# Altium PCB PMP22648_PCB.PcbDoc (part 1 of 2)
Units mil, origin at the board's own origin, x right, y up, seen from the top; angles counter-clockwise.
Board outline 3299.21 x 2751.97 mil, 6 copper layers (Top Layer, GND, GND (Mid2), Signal Layer 3, GND (Mid4), Bottom Layer), stack 107.669 mil thick; 130 components, 60 nets, 290 pads, 212 vias.
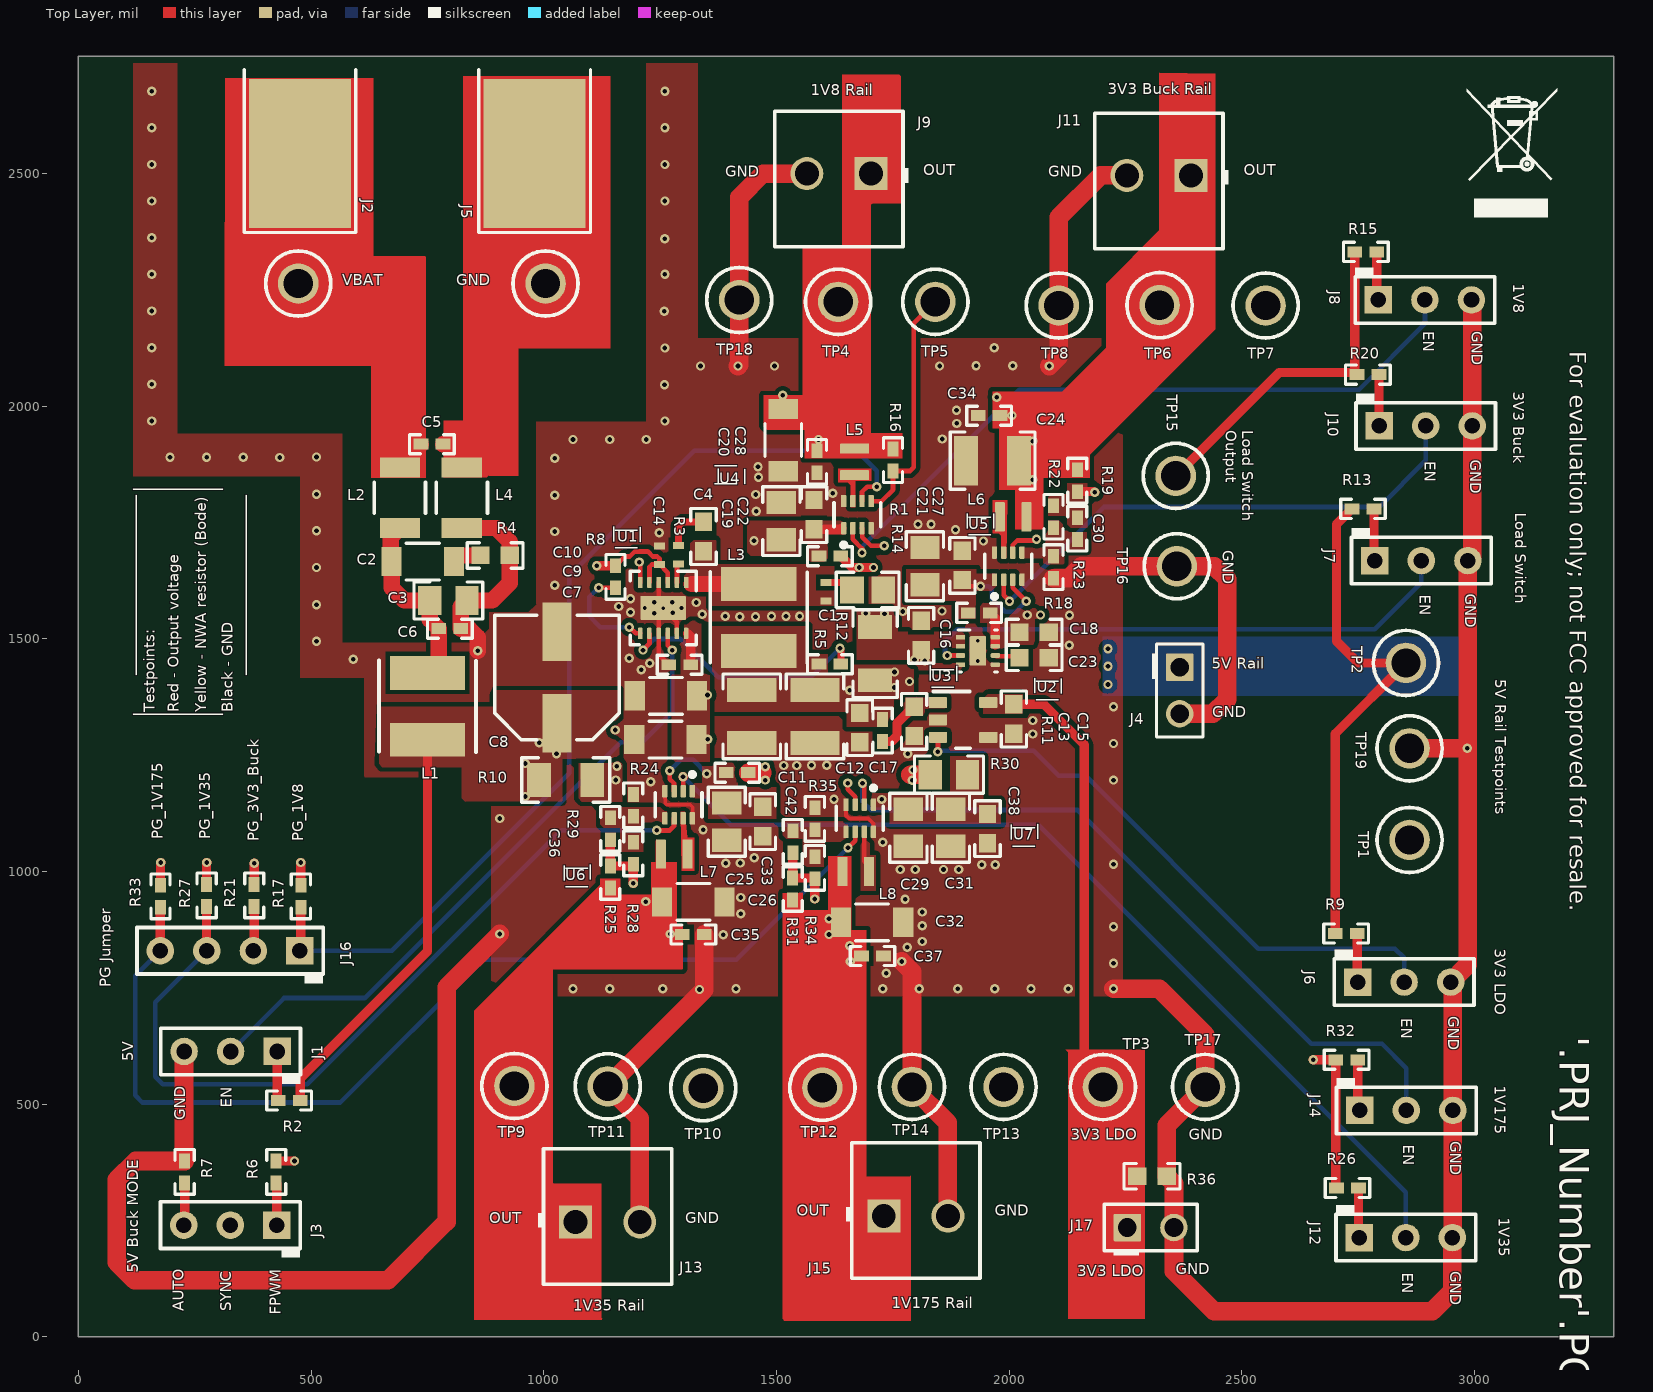
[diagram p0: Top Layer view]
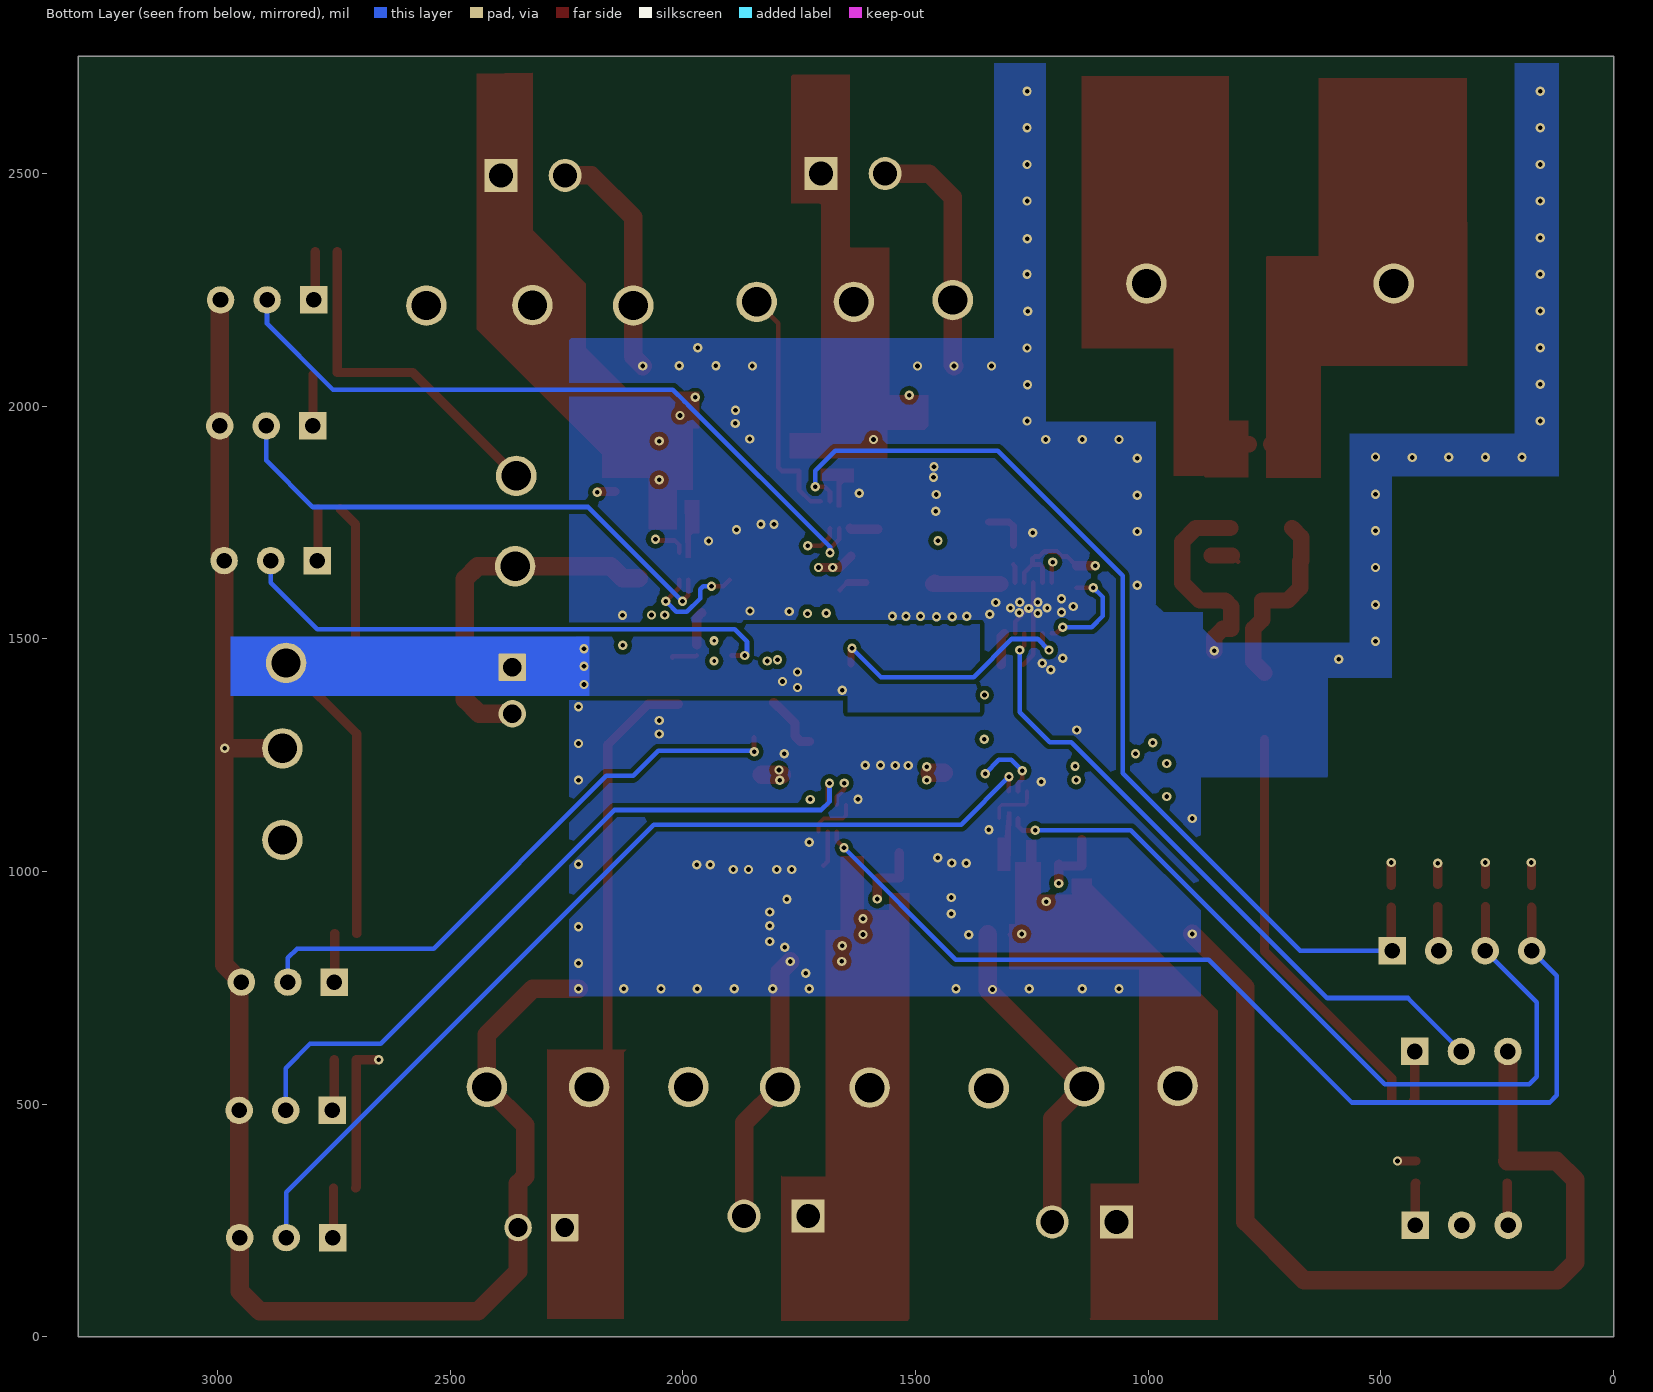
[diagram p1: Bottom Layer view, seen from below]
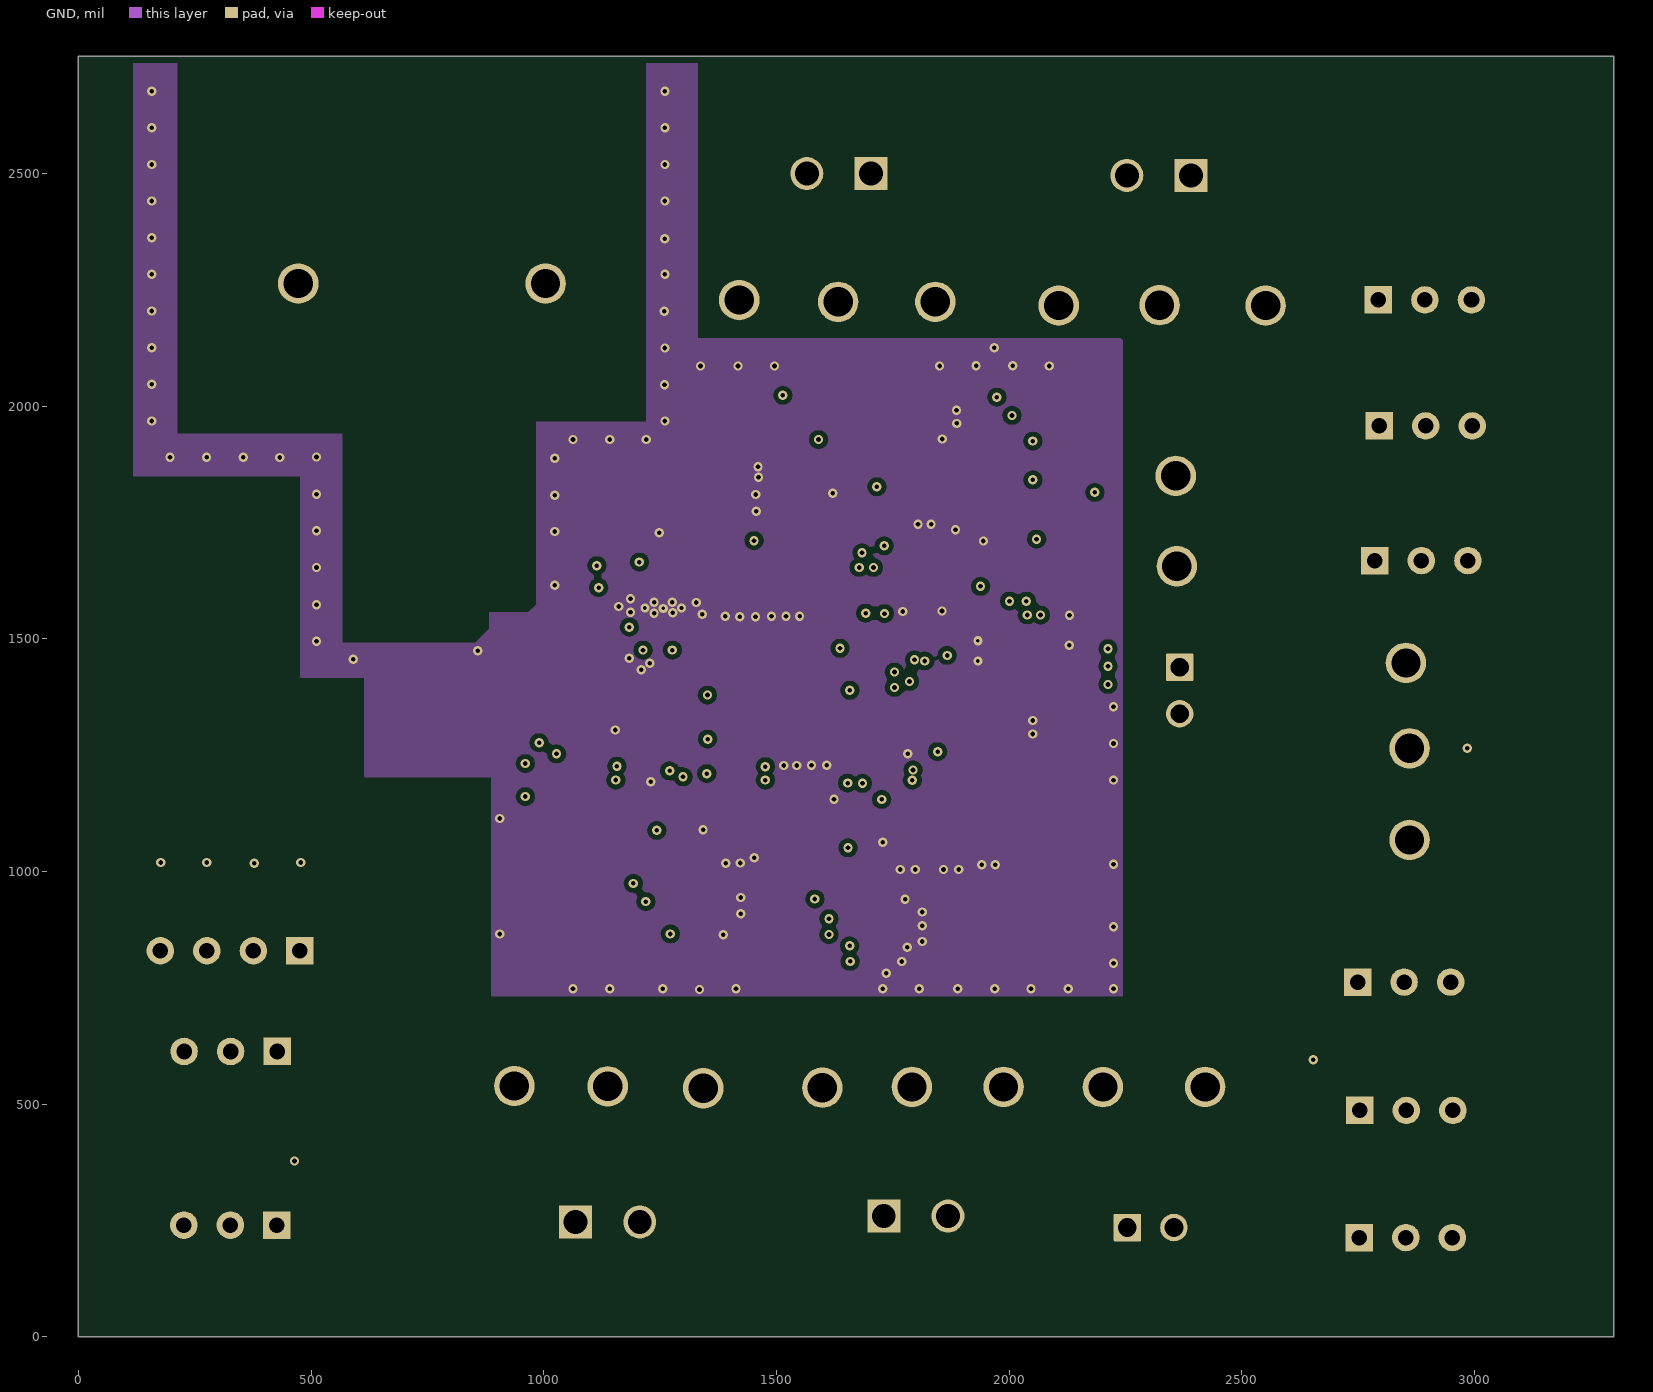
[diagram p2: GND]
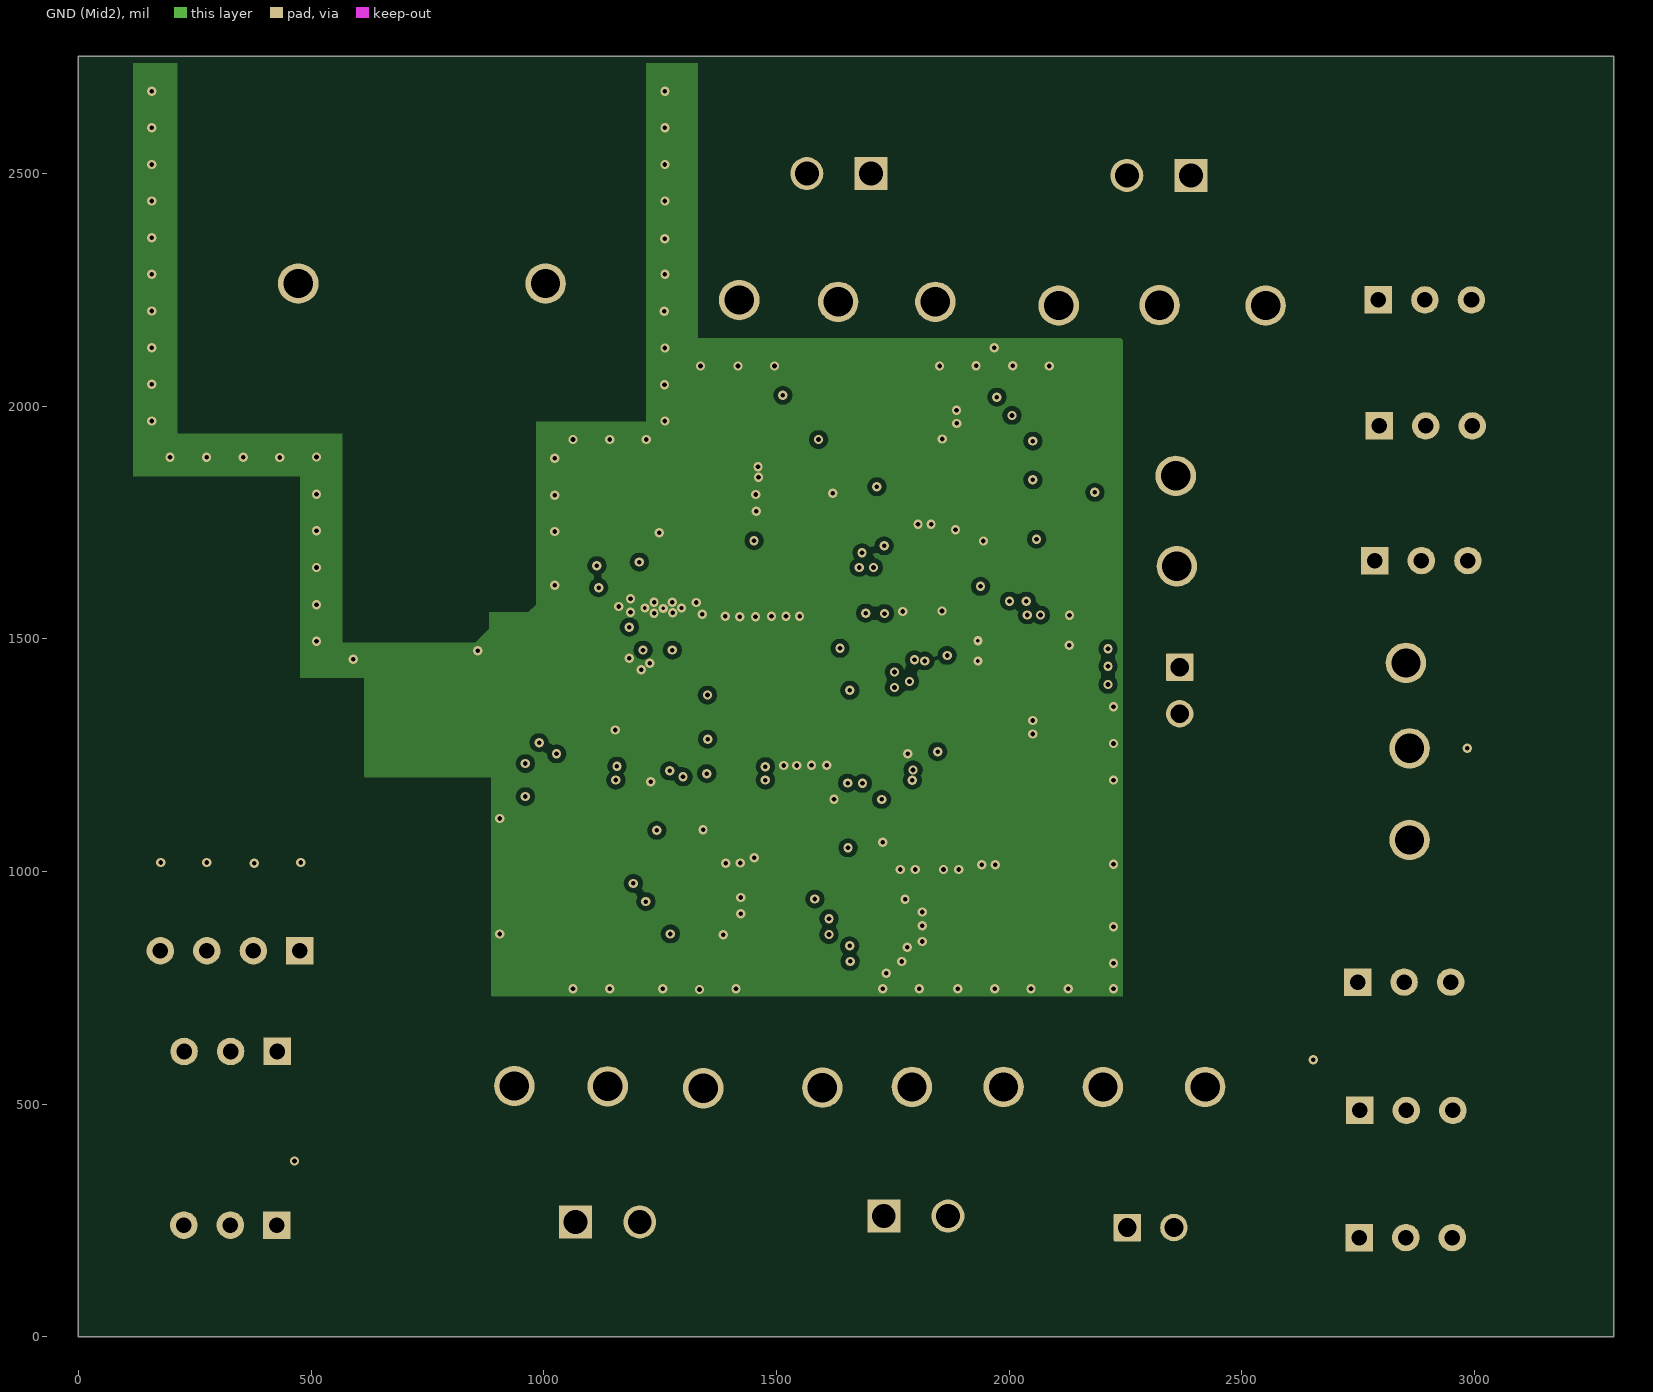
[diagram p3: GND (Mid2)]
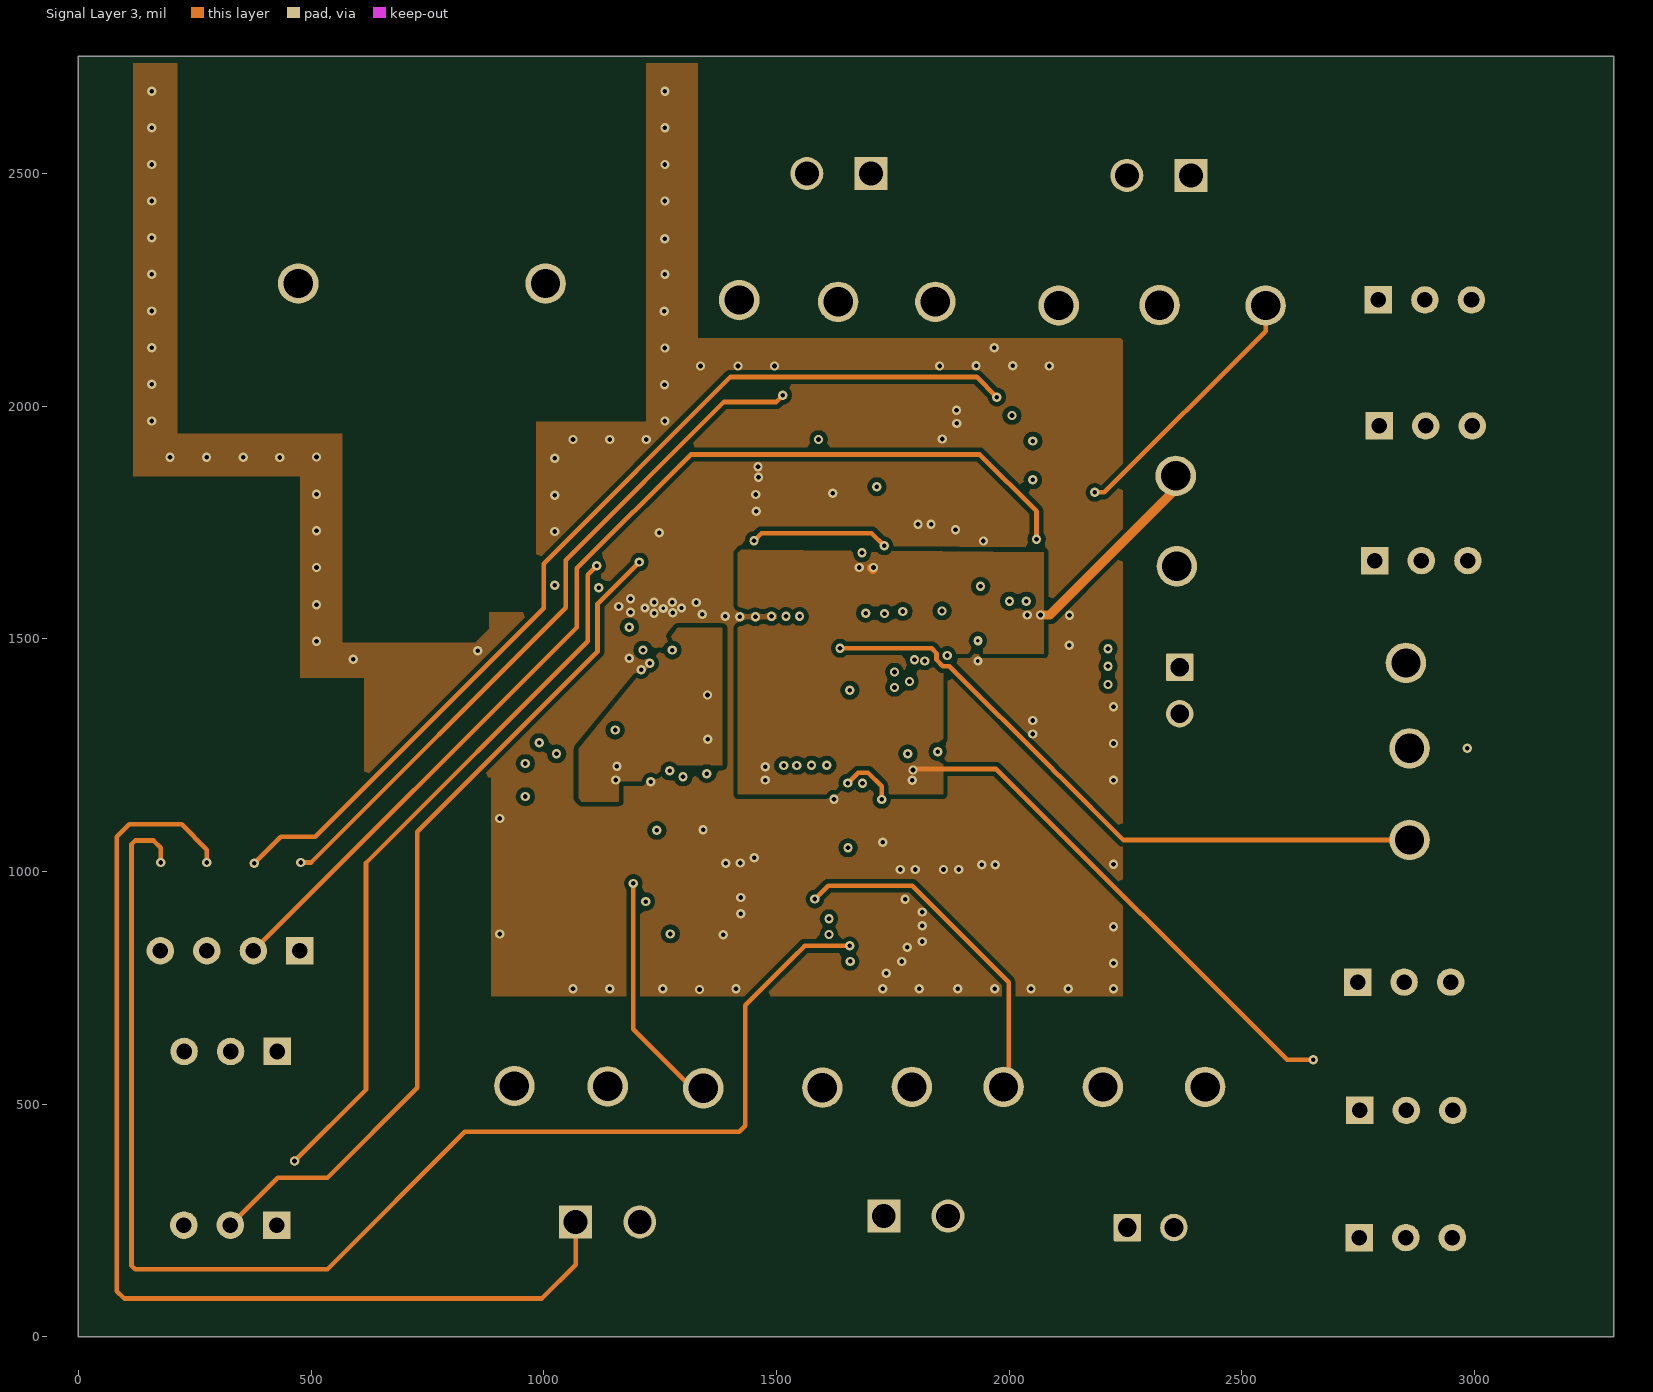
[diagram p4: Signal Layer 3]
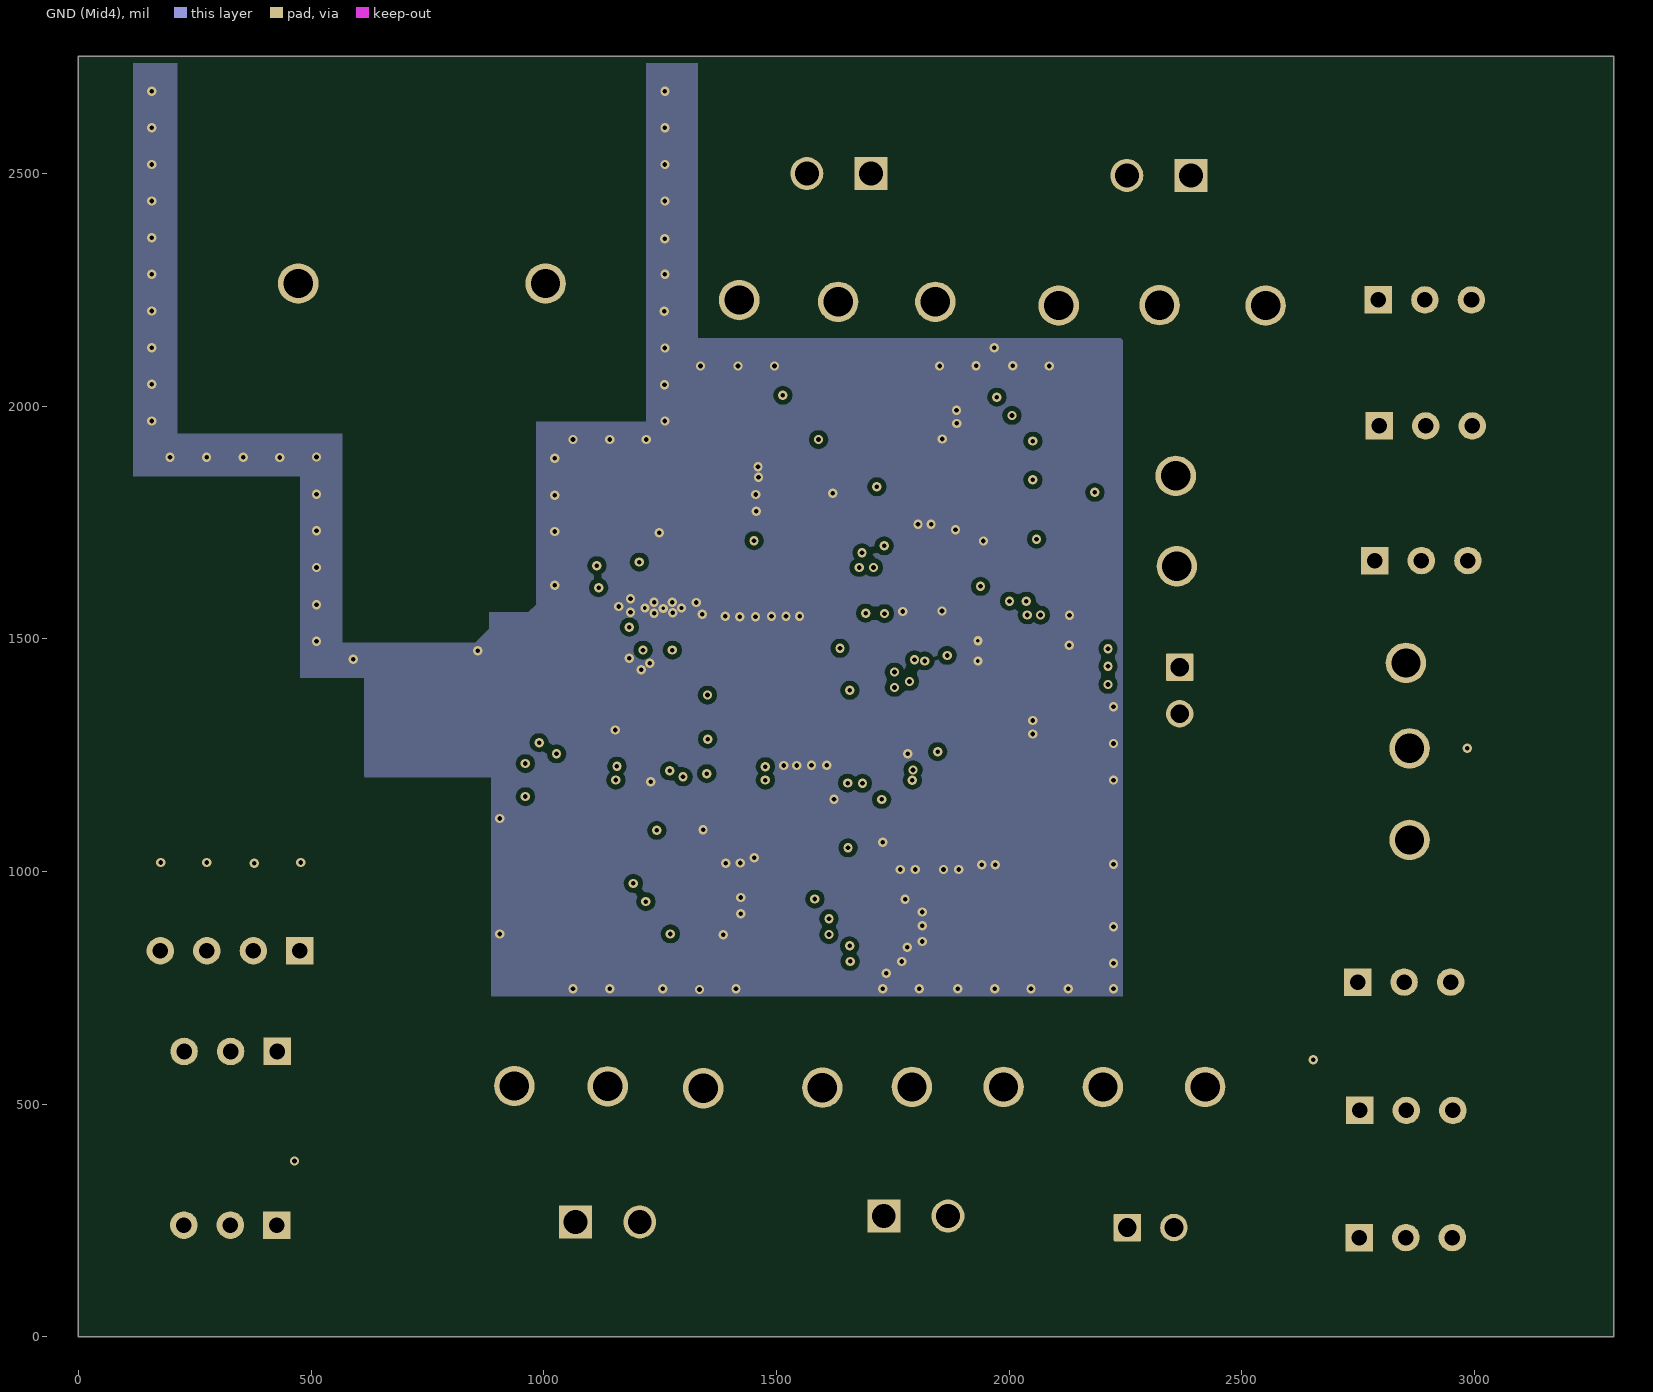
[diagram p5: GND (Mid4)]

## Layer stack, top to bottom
Top Solder: solder mask 0.4, Solder Resist, Dk 3.5
Top Layer: signal copper 1.4
Dielectric 2: dielectric 10, Dk 4.2
GND: signal copper 1.4173
Dielectric 3: dielectric 10, Dk 4.2
GND (Mid2): signal copper 1.4173
Dielectric1: core 59.2, FR-4, Dk 4.8
Signal Layer 3: signal copper 1.4173
Dielectric 4: dielectric 10, Dk 4.2
GND (Mid4): signal copper 1.4173
Dielectric 5: dielectric 10, Dk 4.2
Bottom Layer: signal copper 1.4
Bottom Solder: solder mask 0.4, Solder Resist, Dk 3.5

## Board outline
0,0 3299.21,0 3299.21,2751.97 0,2751.97

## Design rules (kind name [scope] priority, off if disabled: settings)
AcuteAngle [All] p1: minimum=4.50000000000000E+0001 checktracksonly=FALSE
AssemblyTestPointUsage [All] p1: valid=2
BoardOutlineClearance BoardOutlineClearance_MountingHoles [OnCopper and InComponentClass('Mounting Holes')] p1: gap=25 ignorepadtopadclearanceinfootprint=FALSE
BoardOutlineClearance BoardOutlineClearance_Poly [OnCopper and IsPoly] p2: gap=15 ignorepadtopadclearanceinfootprint=FALSE
BoardOutlineClearance [OnCopper and Not InComponentClass('Logo') and not InComponentClass('FiducialMark') and not InRegion(1000,500,4000,800) and not InPoly] p3: gap=30 ignorepadtopadclearanceinfootprint=FALSE
Clearance Clearance_1 [InNamedPolygon('TOP_LAYER_1V8_P020')] p1: gap=10 ignorepadtopadclearanceinfootprint=TRUE except(0: Arc-Hole Track-Hole SMDPad-Hole THPad-Hole Via-Hole Fill-Hole Poly-Hole Region-Hole Text-Hole)
Clearance Clearance_Keepouts [((IsTrack Or IsArc) And Not InPoly) And IsFree and IsKeepOut vs ((IsTrack Or IsArc) And Not InPoly) And IsFree and IsKeepOut] p2: gap=0 ignorepadtopadclearanceinfootprint=FALSE
Clearance Clearance_Poly [InPolygon] p3: gap=10 ignorepadtopadclearanceinfootprint=TRUE
Clearance Clearance_FiducialMark [IsKeepOut and InComponentClass('FiducialMark') vs IsPad and InComponentClass('FiducialMark')] p4: gap=0 ignorepadtopadclearanceinfootprint=FALSE
Clearance [All] p5: gap=7.87 ignorepadtopadclearanceinfootprint=TRUE
ComponentClearance ComponentClearance_MountingHoles_FiducialMarks [InComponentClass('Mounting Holes') vs InComponentClass('FiducialMark')] p1: gap=50 collisioncheckmode=3 verticalgap=10 showdistances=FALSE
ComponentClearance ComponentClearance_Shunt [InComponentClass('Header') vs InComponentClass('Shunt')] p2: gap=0 collisioncheckmode=3 verticalgap=0 showdistances=FALSE
ComponentClearance ComponentClearance_Logo [InComponentClass('Logo')] p3: gap=50 collisioncheckmode=3 verticalgap=10 showdistances=FALSE
ComponentClearance ComponentClearance_ScrewToNut [(HasFootprint('NY PMS 440 0025 PH')) vs (HasFootprint('Keystone_1902C'))] p4: gap=5 collisioncheckmode=3 verticalgap=10 showdistances=FALSE
ComponentClearance ComponentClearance_MountingHoles [InComponentClass('Mounting Holes')] p5: gap=250 collisioncheckmode=3 verticalgap=100000 showdistances=FALSE
ComponentClearance ComponentClearance_SmallPassives [HasFootprint('0201*') or HasFootprint('0402*') or HasFootprint('0508') or HasFootprint('0603*') or HasFootprint('0612') or HasFootprint('0805*') or HasFootprint('0815*') or HasFootprint('0830*') or HasFootprint('1206*') or HasFootprint('1210*') or HasFootprint('1808*') or HasFootprint('1812*') or HasFootprint('1825*') or HasFootprint('2010*') or HasFootprint('2220*') or HasFootprint('2225*') or HasFootprint('2512*') or HasFootprint('2728*') or HasFootprint('3518*') vs HasFootprint('0201*') or HasFootprint('0402*') or HasFootprint('0508') or HasFootprint('0603*') or HasFootprint('0612') or HasFootprint('0805*') or HasFootprint('0815*') or HasFootprint('0830*') or HasFootprint('1206*') or HasFootprint('1210*') or HasFootprint('1808*') or HasFootprint('1812*') or HasFootprint('1825*') or HasFootprint('2010*') or HasFootprint('2220*') or HasFootprint('2225*') or HasFootprint('2512*') or HasFootprint('2728*') or HasFootprint('3518*')] p6: gap=14.96 collisioncheckmode=3 verticalgap=10 showdistances=FALSE
ComponentClearance ComponentClearance_THtoSMT [IsThruComponent vs IsSMTComponent] p7: gap=40 collisioncheckmode=3 verticalgap=30 showdistances=FALSE
ComponentClearance ComponentClearance_THtoTH [IsThruComponent vs IsThruComponent] p8: gap=30 collisioncheckmode=3 verticalgap=30 showdistances=FALSE
ComponentClearance [All] p9: gap=30 collisioncheckmode=3 verticalgap=10 showdistances=FALSE
DiffPairsRouting [All] p1: maxlimit=100 minlimit=10 mostfreqgap=10 toplayer_minwidth=15 toplayer_maxwidth=15 toplayer_prefwidth=15 midlayer1_minwidth=15 midlayer1_maxwidth=15 midlayer1_prefwidth=15 midlayer2_minwidth=15 midlayer2_maxwidth=15 midlayer2_prefwidth=15 midlayer3_minwidth=15 midlayer3_maxwidth=15 midlayer3_prefwidth=15 midlayer4_minwidth=15 midlayer4_maxwidth=15 midlayer4_prefwidth=15 bottomlayer_minwidth=15 bottomlayer_maxwidth=15 bottomlayer_prefwidth=15 maxuncoupledlength=1000
FabricationTestPointUsage TestPointUsage [All] p1: valid=2 allowmultiple=FALSE
FabricationTestpoint Testpoint [All] p1: side=3 testpointundercomponent=TRUE minsize=40 maxsize=100 preferedsize=60 minholesize=0 maxholesize=40 preferedholesize=32 testpointgrid=1 allowsidetop=TRUE allowsidebottom=TRUE usegrid=TRUE gridtolerance=0.01
FanoutControl Fanout_LCC [IsLCC] p1: bgadir=Out bgaviamode=Centered fanoutstyle=Auto fanoutdirection=Alternating viagrid=1 // Fanout_LCC (Default Rule)
FanoutControl Fanout_BGA [IsBGA] p2: bgadir=Out bgaviamode=Centered fanoutstyle=Auto fanoutdirection=Alternating viagrid=1 // Fanout_BGA (Default Rule)
FanoutControl Fanout_Default [All] p4: bgadir=Out bgaviamode=Centered fanoutstyle=Auto fanoutdirection=Alternating viagrid=1 // Fanout_Default (Default Rule)
FanoutControl Fanout_Small [(CompPinCount < 5)] p5: bgadir=Out bgaviamode=Centered fanoutstyle=Auto fanoutdirection=OutThenIn viagrid=1 // Fanout_Small (Default Rule)
HoleSize [All] p1: absolutevalues=TRUE maxlimit=251 minlimit=7.87 maxpercent=80.000 minpercent=20.000
MinimumAnnularRing MinimumAnnularRing_ThermalPadVias [IsVia and InAnyComponent] p1: minimumring=5
MinimumAnnularRing [All] p2: minimumring=5
MinimumSolderMaskSliver MinimumSolderMaskSliver_Logo [InComponentClass('Logo') vs InComponentClass('Logo')] p1: minsoldermaskwidth=0.7
MinimumSolderMaskSliver [All] p2: minsoldermaskwidth=3.94
PlaneConnect [All] p1: planeconnectstyle=Direct reliefexpansion=10 reliefentries=4 reliefconductorwidth=10 reliefairgap=10
PolygonConnect PolygonConnect_1 [All vs IsNamedPolygon('TOP_LAYER_NETC1_2_P004')] p1: connectstyle=Direct reliefconductorwidth=10 reliefentries=4 polygonreliefangle="90 Angle" airgapwidth=10
PolygonConnect [All] p2: connectstyle=Direct reliefconductorwidth=10 reliefentries=4 polygonreliefangle="90 Angle" airgapwidth=10
RoutingVias ThermalPadVias [IsVia and InAnyComponent] p1: holewidth=7.87 width=19.68 viastyle="Through Hole" minholewidth=7.87 minwidth=19.68 maxholewidth=12.99 maxwidth=23.62
RoutingVias [All] p2: holewidth=16 width=34 viastyle="Through Hole" minholewidth=5 minwidth=10 maxholewidth=40 maxwidth=65
SilkToBoardRegionClearance [Not ((IsComment or IsDesignator) And (Hide <> 'False')) and not InRegion(1000,500,4000,800)] p1:
SilkToSilkClearance SilkToSilkClearance_Pb-FreeLogo [(HasFootprint('Pb-Free_Overlay_Medium') OR HasFootprint('Pb-Free_Overlay_Small')) vs (HasFootprint('Pb-Free_Overlay_Medium') OR HasFootprint('Pb-Free_Overlay_Small'))] p1: silktosilkclearance=0
SilkToSilkClearance [All] p2: silktosilkclearance=0
SilkToSolderMaskClearance SilkToComponentPadClearance [(IsPad or IsFill or IsRegion) and InAnycomponent] p1: minsilkscreentomaskgap=0 clearancetoexposedcopper=TRUE
SilkToSolderMaskClearance "Silk to Solder Mask Opening" [All] p2: minsilkscreentomaskgap=0 clearancetoexposedcopper=FALSE
SolderMaskExpansion [All] p1: expansion=1.97
UnRoutedNet [All] p1: checkbadconnections=TRUE
Width [All] p1: maxlimit=100 minlimit=6 preferedwidth=10 checkconnectedcopper=TRUE
14 further rules are at their usual default settings.

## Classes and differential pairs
component class "PMP22648_PoL DCDC": C19 C20 C21 C22 C24 C25 C26 C27 C28 C29 C30 C31 C32 C33 C34 C35 C36 C37 C38 C42 J8 J9 J10 J11 J12 J13 J14 J15 J16 L5 L6 L7 L8 Logo1 R14 R15 R16 R17 R18 R19 R20 R21 R22 R23 R24 R25 R26 R27 R28 R29 R30 R31 R32 R33 R34 R35 TP4 TP5 TP6 TP7 TP8 TP9 TP10 TP11 TP12 TP13 TP14 TP18 U4 U5 U6 U7 ""
component class "PMP22648_Bus + LDO + LS": C1 C2 C3 C4 C5 C6 C7 C8 C9 C10 C11 C12 C13 C14 C15 C16 C17 C18 C23 GND J1 J2 J3 J4 J5 J6 J7 J17 L1 L2 L3 L4 R1 R2 R3 R4 R5 R6 R7 R8 R9 R10 R11 R12 R13 R36 TP1 TP2 TP3 TP15 TP16 TP17 TP19 U1 U2 U3 VBAT
component class Header: J1 J3 J4 J6 J7 J8 J10 J12 J14 J16 J17

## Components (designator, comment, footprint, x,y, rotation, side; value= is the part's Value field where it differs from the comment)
C1 "GCM155R71H391KA37D" 0402S 1606.85,1601.35 r270 top value=390pF
C2 "GCM31CC71H475KA03L" 1206_180 740.18,1666.25 r0 top value=4.7uF
C3 "GCM21BR71H105KA03K" 0805_HV 795.3,1582.64 r0 top value=1uF
C4 "GCM155R71C224KE02" 0603 1343.41,1720.16 r270 top value=0.22uF
C5 "GCM155R71H104KE02D" 0402 759.86,1918.43 r0 top value=0.1uF
C6 "GCM155R71H104KE02D" 0402 798.34,1521.96 r0 top value=0.1uF
C7 "GCM31CC71H475KA03L" 1206_180 1261.44,1283.75 r180 top value=4.7uF
C8 "EEEFT1H470AP" Panasonic_D 1028.45,1417.01 r90 top value=47uF
C9 "GCM31CC71H475KA03L" 1206_180 1262.69,1377.64 r180 top value=4.7uF
C10 "GCM155R71H104KE02D" 0402 1292.23,1444.57 r180 top value=0.1uF
C11 "CL32B226KOJVPNE" 1210_270 1447.19,1333.55 r270 top value=22uF
C12 "CL32B226KOJVPNE" 1210_270 1583.01,1333.55 r270 top value=22uF
C13 "GCM188R71C105KA64J" 0603 1795.85,1322.83 r270 top value=1uF
C14 "GCM155C71A105KE38D" 0402_070 1248.92,1680.01 r90 top value=1uF
C15 "GCM188R71C105KA64J" 0603 2010.36,1328.04 r270 top value=1uF
C16 "GCM188R71C105KA64J" 0603 1811.02,1507.57 r90 top value=1uF
C17 "GCM188R71C104KA37J" 0603 1679.13,1309.34 r270 top value=0.1uF
C18 "GCM188R71C104KA37J" 0603 2053.8,1514.84 r0 top value=0.1uF
C19 "CGA4J1X7S1C106K125AC" 0805_HV 1510.58,1753.33 r90 top value=10uF
C20 "GCM31CR70J226ME23L" 1206_180 1514.52,1927.31 r270 top value=22uF
C21 "CGA4J1X7S1C106K125AC" 0805_HV 1819.19,1656.31 r90 top value=10uF
C22 "GCM188R71C104KA37J" 0603 1580.81,1767.11 r90 top value=0.1uF
C23 "CGA3E2C0G1H221J080AA" 0603 2053.8,1459.38 r0 top value=220pF
C24 "CL32B226KOJVPNE" 1210_270 1964.59,1883.23 r180 top value=22uF
C25 "CGA4J1X7S1C106K125AC" 0805_HV 1393.33,1107.33 r270 top value=10uF
C26 "GCM31CR70J226ME23L" 1206_180 1321.48,934.86 r0 top value=22uF
C27 "GCM188R71C104KA37J" 0603 1899.82,1658.28 r90 top value=0.1uF
C28 "GCM155R71A104KA55D" 0402 1587.35,1880.48 r270 top value=0.1uF
C29 "CGA4J1X7S1C106K125AC" 0805_HV 1783.46,1094.3 r270 top value=10uF
C30 "GCM1555C1H100JA16D" 0402 2146.7,1737.19 r270 top value=10pF
C31 "CGA4J1X7S1C106K125AC" 0805_HV 1875,1094.3 r270 top value=10uF
C32 "GCM31CR70J226ME23L" 1206_180 1705.58,890.94 r0 top value=22uF
C33 "GCM188R71C104KA37J" 0603 1470.73,1107.64 r270 top value=0.1uF
C34 "GCM155R71A104KA55D" 0402 1957.05,1979.69 r180 top value=0.1uF
C35 "GCM155R71A104KA55D" 0402 1321.48,864.98 r0 top value=0.1uF
C36 "GCM1555C1H100JA16D" 0402 1143.07,1091.84 r90 top value=10pF
C37 "GCM155R71A104KA55D" 0402 1706.6,818.78 r0 top value=0.1uF
C38 "GCM188R71C104KA37J" 0603 1953.74,1092.33 r270 top value=0.1uF
C42 "GCM1555C1H100JA16D" 0402 1535.24,1063.95 r90 top value=10pF
GND "5011" Keystone5011 1003.94,2263.78 r0 top
J1 "800-10-003-10-001000" Mill-Max_800-10-003-10-001000 327.16,613.55 r180 top
J2 "6091" 6091 476.38,2728.31 r270 top
J3 "800-10-003-10-001000" Mill-Max_800-10-003-10-001000 326.69,240.33 r180 top
J4 "PEC02SAAN" CONN_PEC02SAAN 2366.69,1389.21 r270 top
J5 "6092" 6092 980.31,2728.31 r270 top
J6 "800-10-003-10-001000" Mill-Max_800-10-003-10-001000 2848.93,762.65 r0 top
J7 "800-10-003-10-001000" Mill-Max_800-10-003-10-001000 2885.94,1668.34 r0 top
J8 "800-10-003-10-001000" Mill-Max_800-10-003-10-001000 2893.65,2228.51 r0 top
J9 "691214000000" Wurth_691214110002 1634.4,2500 r180 top
J10 "800-10-003-10-001000" Mill-Max_800-10-003-10-001000 2895.32,1957.78 r0 top
J11 "691214000000" Wurth_691214110002 2322.06,2496.06 r180 top
J12 "800-10-003-10-001000" Mill-Max_800-10-003-10-001000 2852.59,213.69 r0 top
J13 "691214000000" Wurth_691214110002 1137.53,247.19 r0 top
J14 "800-10-003-10-001000" Mill-Max_800-10-003-10-001000 2853.64,486.95 r0 top
J15 "691214000000" Wurth_691214110002 1799.68,259.84 r0 top
J16 "800-10-004-10-001000" Mill-Max_800-10-004-10-001000 326.17,829.94 r180 top
J17 "PEC02SAAN" CONN_PEC02SAAN 2304.33,235.24 r0 top
L1 "LQH5BPN1R5N38L" LQH5BPN_38 750.34,1355.21 r270 top value=1.5uH
L2 "FBMH3225HM601NT" 1210_280 691.03,1803.45 r270 top value="600 ohm"
L3 "LQH5BPN2R2N38L" LQH5BPN_38 1462.23,1546.15 r270 top value=2.2uH
L4 "FBMH3225HM601NT" 1210_280 824.11,1803.45 r270 top value="600 ohm"
L5 "DFE201612E-R47M=P2" DFE201612E 1668.06,1880.48 r90 top value=470nH
L6 "DFE201612E-R47M=P2" DFE201612E 2008.67,1762.36 r0 top value=470nH
L7 "DFE201612E-R47M=P2" DFE201612E 1280.42,1037.7 r180 top value=470nH
L8 "DFE201612E-R47M=P2" DFE201612E 1670.5,1000.3 r180 top value=470nH
Logo1 "WEEE logo" WEEE_Minimum 3078.74,2578.74 r0 top
Logo2 "FCC disclaimer" FCC_disclaimer 3374.92,623.48 r90 top
R1 "ERJ-6GEYJ3R0V" 0805 1696.09,1605.21 r180 top value=3.0
R2 "RMCF0402FT100K" 0402 453.15,508.23 r0 top value=100k
R3 "CRCW04020000Z0EDHP" 0402S 1289.98,1680.86 r270 top value=0
R4 "ERJ-3RQFR51V" 0603 895.69,1679.44 r180 top value=0.51
R5 "ERJ-2RKF49R9X" 0402 1615.06,1445.76 r180 top value=49.9
R6 "RMCF0402FT100K" 0402 425.2,354.66 r270 top value=100k
R7 "RMCF0402FT100K" 0402 228.35,354.66 r270 top value=100k
R8 "RMCF0402FT100K" 0402 1154.43,1633.55 r90 top value=100k
R9 "CRCW040210K0FKED" 0402 2724.41,867.09 r0 top value=10.0k
R10 "CRCW12060000Z0EAHP" 1206 1047.24,1196.85 r0 top value=0
R11 "CRCW04020000Z0EDHP" 0402 1728.26,1303.15 r270 top value=0
R12 "CRCW12060000Z0EAHP" 1206 1712.29,1468.5 r90 top value=0
R13 "CRCW040210K0FKED" 0402 2760.55,1779.53 r0 top value=10.0k
R14 "CRCW04020000Z0EDHP" 0402 1615.06,1677.9 r180 top value=0
R15 "CRCW040210K0FKED" 0402 2766.63,2331.81 r0 top value=10.0k
R16 "ERJ-2RKF49R9X" 0402 1750.74,1884.41 r90 top value=49.9
R17 "RMCF0402FT100K" 0402 478.15,946.85 r90 top value=100k
R18 "CRCW04020000Z0EDHP" 0402 1935.69,1556.03 r180 top value=0
R19 "ERJ-2RKF49R9X" 0402 2146.7,1840.3 r90 top value=49.9
R20 "CRCW040210K0FKED" 0402 2771.2,2068.08 r0 top value=10.0k
R21 "RMCF0402FT100K" 0402 377.95,948.82 r90 top value=100k
R22 "CRCW0402232KFKED" 0402 2095.52,1762.55 r90 top value=232k
R23 "ERJ-2RKF5102X" 0402 2095.52,1654.28 r90 top value=51.0k
R24 "CRCW04020000Z0EDHP" 0402 1415.85,1212.65 r180 top value=0
R25 "ERJ-2RKF49R9X" 0402 1143.07,988.49 r270 top value=49.9
R26 "CRCW040210K0FKED" 0402 2727.2,320.23 r0 top value=10.0k
R27 "RMCF0402FT100K" 0402 275.59,948.82 r90 top value=100k
R28 "CRCW040264K9FKED" 0402 1192.54,1039.42 r270 top value=64.9k
R29 "ERJ-2RKF5102X" 0402 1192.54,1142.3 r270 top value=51.0k
R30 "PMR10EZPJ000" 0805_HV 1870.85,1208.35 r0 top value=0
R31 "ERJ-2RKF49R9X" 0402 1535.15,962.74 r270 top value=49.9
R32 "CRCW040210K0FKED" 0402 2725.42,595.59 r0 top value=10.0k
R33 "RMCF0402FT100K" 0402 176.69,946.85 r90 top value=100k
R34 "ERJ-2RKF4992X" 0402 1582.67,1008.15 r270 top value=49.9k
R35 "ERJ-2RKF5102X" 0402 1582.67,1113.47 r270 top value=51.0k
R36 "CRCW0603324RFKEA" 0603 2307.09,345.47 r180 top value=324
TP1 "5014" Keystone5014 2860.66,1068.03 r0 top
TP2 "5010" Keystone5010 2852.78,1448.41 r0 top
TP3 "5010" Keystone5010 2201.68,537.09 r0 top
TP4 "5010" Keystone5010 1632.73,2224.41 r180 top
TP5 "5014" Keystone5014 1841.54,2224.41 r0 top
TP6 "5010" Keystone5010 2323.38,2217.31 r180 top
TP7 "5014" Keystone5014 2551.31,2216.54 r0 top
TP8 "5011" Keystone5011 2106.85,2216.54 r180 top
TP9 "5010" Keystone5010 937.01,539.37 r0 top
TP10 "5014" Keystone5014 1342.8,534.59 r0 top
TP11 "5011" Keystone5011 1137.53,538.53 r0 top
TP12 "5010" Keystone5010 1598.9,535.76 r0 top
TP13 "5014" Keystone5014 1988.19,537.4 r0 top
TP14 "5011" Keystone5011 1791.34,537.4 r0 top
TP15 "5010" Keystone5010 2358.27,1850.39 r270 top
TP16 "5011" Keystone5011 2360.54,1656.36 r180 top
TP17 "5011" Keystone5011 2421.26,537.4 r0 top
TP18 "5011" Keystone5011 1420.14,2228.35 r180 top
TP19 "5011" Keystone5011 2860.66,1264.88 r0 top
U1 "LM63625DQDRRRQ1" DRR0012E 1256.79,1566.63 r270 top
U2 "TLV73333PQDBVRQ1" DBV0005A_N 1901.29,1325.98 r0 top
U3 "TPS22965QWDSGRQ1" DSG0008B 1933.07,1474.33 r0 top
U4 "TPS6285010MQDRLRQ1" DRL0008A-MFG 1674.15,1767.11 r90 top
U5 "TPS628501QDRLRQ1" DRL0008A-MFG 1998.24,1656.31 r90 top
U6 "TPS628501QDRLRQ1" DRL0008A-MFG 1289.98,1143.75 r270 top
U7 "TPS628502QDRLRQ1" DRL0008A-MFG 1679.13,1114.62 r270 top
VBAT "5010" Keystone5010 472.57,2263.78 r270 top

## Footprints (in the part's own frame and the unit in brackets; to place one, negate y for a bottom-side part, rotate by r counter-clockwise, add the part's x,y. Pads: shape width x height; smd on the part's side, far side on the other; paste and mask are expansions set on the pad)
0402 [mm] "0402 from SM-752 data"
  rect 0.8x0.6 smd: 1(-0.6,0) 2(0.6,0)
  silkscreen extent -1.22,-0.52 1.22,0.52, body extent -0.55,-0.3 0.55,0.3, height 0.6
0402_070 [mil] "SMD, 2-Leads, Body 1.2x0.7mm, Height 0.7mm"
  rect 15x24 smd: 1(-20,0) 2(20,0)
  body extent -24,-14 24,14, height 28
0402S [mil] "Based on C0402S footprint from PADS legacy"
  rect 15x24 smd: 1(-20,0) 2(20,0)
  body extent -22,-12 22,12, height 24
0603 [mm] "0603 from SM-752 data"
  rect 1x0.95 smd: 1(-0.8,0) 2(0.8,0)
  silkscreen extent -1.52,-0.69 1.52,0.69, body extent -0.87,-0.47 0.87,0.47, height 1
0805 [mm] "0805 from SM-752 data"
  rect 1.3x1.5 smd: 1(-0.85,0) 2(0.85,0)
  silkscreen extent -1.72,-0.97 1.72,0.97, body extent -1.1,-0.72 1.1,0.72, height 1.45
0805_HV [mil] "0805 with 30mil clearance between pads"
  rect 50x63 smd: 1(-40,0) 2(40,0)
  silkscreen extent -74,-40 74,40, body extent -43,-29 43,29, height 57
1206 [mm] "1206 from SM-752 data"
  rect 1.3x1.85 smd: 1(-1.45,0) 2(1.45,0)
  silkscreen extent -2.4,-1.21 2.4,1.21, body extent -1.7,-0.9 1.7,0.9, height 1.35
1206_180 [mm] "1206_180"
  rect 1.1x1.6 smd: 1(-1.7,0) 2(1.7,0)
  silkscreen extent -0.9,-1 0.9,1, body extent -1.75,-0.95 1.75,0.95, height 1.8
1210_270 [mm] "1210"
  rect 1.3x2.7 smd: 1(-1.45,0) 2(1.45,0)
  silkscreen extent -2.32,-1.57 2.32,1.57, body extent -1.7,-1.35 1.7,1.35, height 2.7
1210_280 [mm] "SMD, 2-Leads, Body 3.6x2.8mm, Height 2.8mm"
  rect 1.1x2.2 smd: 1(-1.65,0) 2(1.65,0)
  silkscreen extent -0.84,-1.4 0.84,1.4, body extent -1.8,-1.4 1.8,1.4, height 2.8
6091 [mil] "Keystone Insulated End Launch Banana Jack"
  rect 320x220 smd: 1(185,0)
  silkscreen extent 5,-120 355,120, body extent -666,-216 271,216, height 227
6092 [mil] "Keystone Insulated End Launch Banana Jack"
  rect 320x220 smd: 1(185,0)
  silkscreen extent 5,-120 355,120, body extent -666,-216 271,216, height 227
CONN_PEC02SAAN [mm] "SULLINS"
  rrect7% 1.5x1.5 hole 1.016: 1(-1.27,0)
  round 1.5 hole 1.016: 2(1.27,0)
  silkscreen extent -2.54,-1.52 2.54,1.27, body extent -2.54,-1.27 2.54,1.27, height 8.38
DBV0005A_N [mm] "SOT23, 5-Leads, Body 2.9x1.6mm, Pitch 0.95mm, Lead Span 2.8mm, IPC Medium Density"
  rrect17% 1x0.6 smd: 1(-1.375,0.95) 2(-1.375,0) 3(-1.375,-0.95) 4(1.375,-0.95) 5(1.375,0.95)
  silkscreen extent -1.63,-1.55 0.38,1.55, body extent -1.42,-1.46 1.42,1.46, height 1.09
DFE201612E [mm] "MuRata recommended"
  rrect18% 0.55x1.6 smd: 1(-0.725,0) 2(0.725,0)
  body extent -1.1,-0.9 1.1,0.9, height 1.2
DRL0008A-MFG [mm]
  rrect33% 0.67x0.3 smd paste+0 mask+0: 1(-0.74,0.75) 2(-0.74,0.25) 3(-0.74,-0.25) 4(-0.74,-0.75) 5(0.74,-0.75) 6(0.74,-0.25) 7(0.74,0.25) 8(0.74,0.75)
  silkscreen extent -1.77,-1.28 0.65,1.28, body extent -1.17,-1.35 1.17,1.35, height 0.25
DRR0012E [mm] "WSON-12"
  rrect40% 0.62x0.25 smd: 1(-1.39,1.25) 2(-1.39,0.75) 3(-1.39,0.25) 4(-1.39,-0.25) 5(-1.39,-0.75) 6(-1.39,-1.25) 7(1.39,-1.25) 8(1.39,-0.75) 9(1.39,-0.25) 10(1.39,0.25) 11(1.39,0.75) 12(1.39,1.25)
  rrect8% 1.3x2.5 smd paste-1.7: 13(0,0)
  silkscreen extent -2,-1.8 2,1.8, body extent -1.5,-1.5 1.5,1.5, height 0.81
DSG0008B [mm] "SON, 8-Leads, Body 2x2mm, Pitch 0.5mm, Thermal Pad 1.6x0.9mm, TI Recommended"
  rrect14% 0.9x0.7 on Top Paste: 0(0,-0.45) 0(0,0.45)
  rrect40% 0.5x0.25 smd: 1(-0.95,0.75) 2(-0.95,0.25) 3(-0.95,-0.25) 4(-0.95,-0.75) 5(0.95,-0.75) 6(0.95,-0.25) 7(0.95,0.25) 8(0.95,0.75)
  rrect11% 0.9x1.6 smd paste-0.45: 9(0,0)
  silkscreen extent -1.07,-1.15 1.07,1.15, body extent -1,-1 1,1, height 0.77
FCC_disclaimer [mil]
Keystone5010 [mil] "Keystone Multipurpose loops"
  round 87 hole 63: 1(0,0)
  silkscreen extent -70,-70 70,70, body extent -63,-63 63,62, height 319
Keystone5011 [mil] "Keystone Multipurpose loops"
  round 87 hole 63: 1(0,0)
  silkscreen extent -70,-70 70,70, body extent -63,-63 63,62, height 319
Keystone5014 [mil] "Keystone Multipurpose loops"
  round 87 hole 63: 1(0,0)
  silkscreen extent -70,-70 70,70, body extent -63,-63 63,62, height 319
LQH5BPN_38 [mm] "MURATA"
  rect 1.85x4.1 smd: 1(-1.825,0) 2(1.825,0)
  silkscreen extent -2.5,-2.65 2.5,2.65, body extent -2.55,-2.55 2.55,2.55, height 4
Mill-Max_800-10-003-10-001000 [mm] "Mill-Max"
  rect 1.5x1.5 hole 0.85: 1(-2.54,0)
  round 1.5 hole 0.85: 2(0,0) 3(2.54,0)
  silkscreen extent -3.81,-1.27 3.81,1.78, body extent -3.81,-1.27 3.81,1.27, height 8.13
Mill-Max_800-10-004-10-001000 [mm] "Mill-Max"
  rect 1.5x1.5 hole 0.85: 1(-3.81,0)
  round 1.5 hole 0.85: 2(-1.27,0) 3(1.27,0) 4(3.81,0)
  silkscreen extent -5.08,-1.27 5.08,1.78, body extent -5.08,-1.27 5.08,1.27, height 8.13
Panasonic_D [mm] "SMD, 2-Leads, Dia 6.3mm"
  rect 3.2x1.6 smd: 1(-2.5,0) 2(2.5,0)
  silkscreen extent -3.4,-3.4 3.4,3.4, body extent -3.4,-3.4 3.4,3.4, height 6.11
WEEE_Minimum [mil] "WEEElie bin"
  silkscreen extent -95,-172 99,104
Wurth_691214110002 [mm] "Receptacle, 3.5mm, 2x1, TH"
  rect 1.8x1.8 hole 1.3: 1(-1.75,0)
  round 1.8 hole 1.3: 2(1.75,0)
  silkscreen extent -3.8,-3.4 3.5,4, body extent -3.9,-3.4 3.5,4, height 8.5

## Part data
C1: library part CMP-0080703-2, "CAP, CERM, 390 pF, 50 V,+/- 10%, X7R, AEC-Q200 Grade 1, 0402", Cap_Case=0402, Manufacturer=MuRata, Supplier Part Number 1=81-GCM155R71H391KA7D, TempCo=X7R, Tolerance_%=10%, Value2=50V, ValueDisplayed=390pF
C2 C7 C9: library part CMP-0085643-1, "CAP, CERM, 4.7 µF, 50 V,+/- 10%, X7S, AEC-Q200 Grade 1, 1206", Cap_Case=1206, Manufacturer=MuRata, TempCo=X7S, Tolerance_%=10%, Value2=50V, ValueDisplayed=4.7µF
C3: library part CMP-0086249-1, "CAP, CERM, 1 µF, 50 V,+/- 10%, X7R, AEC-Q200 Grade 1, 0805", Cap_Case=0805, Manufacturer=MuRata, TempCo=X7R, Tolerance_%=10%, Value2=50V, ValueDisplayed=1µF
C4: library part CMP-0007125-4, "CAP, CERM, 0.22 uF, 16 V, +/- 10%, X7R, AEC-Q200 Grade 1, 0603", Cap_Case=0603, Manufacturer=MuRata, Supplier Part Number 1=490-10671-1-ND, TempCo=X7R, Tolerance_%=10%, Value1=Unknown, Value2=16V, ValueDisplayed=0.22uF
C5 C6 C10: library part CMP-0006356-1, "CAP, CERM, 0.1 uF, 50 V, +/- 10%, X7R, AEC-Q200 Grade 1, 0402", Cap_Case=0402, Manufacturer=MuRata, Supplier Part Number 1=490-10672-1-ND, TempCo=X7R, Tolerance_%=10%, Value1=Unknown, Value2=50V, ValueDisplayed=0.1uF
C8: library part CMP-0011204-2, "CAP, AL, 47 uF, 50 V, +/- 20%, 0.68 ohm, AEC-Q200 Grade 2, SMD", Cap_Case=6.3x5.8mm, Manufacturer=Panasonic, Supplier Part Number 1=PCE5023CT-ND, Tolerance_%=20%, Value1="0.68 ohm", Value2=50V, ValueDisplayed=47uF
C11 C12 C24: library part CMP-0083755-1, "CAP, CERM, 22 µF, 16 V,+/- 10%, X7R, AEC-Q200 Grade 1, 1210", Cap_Case=1210, Manufacturer="Samsung Electro-Mechanics", TempCo=X7R, Tolerance_%=10%, Value2=16V, ValueDisplayed=22µF
C13 C15 C16: library part CMP-0079154-1, "CAP, CERM, 1 µF, 16 V,+/- 10%, X7R, AEC-Q200 Grade 1, 0603", Cap_Case=0603, Manufacturer=MuRata, Supplier Part Number 1=490-12657-1-ND, TempCo=X7R, Tolerance_%=10%, Value2=16V, ValueDisplayed=1µF
C14: library part CMP-0006349-2, "CAP, CERM, 1 uF, 10 V, +/- 10%, X7S, AEC-Q200 Grade 1, 0402", Cap_Case=0402, Manufacturer=MuRata, Supplier Part Number 1=81-GCM155C71A105KE8D, TempCo=X7S, Tolerance_%=10%, Value1=Unknown, Value2=10V, ValueDisplayed=1uF
C17 C18 C22 C27 C33 C38: library part CMP-0007135-2, "CAP, CERM, 0.1 uF, 16 V, +/- 10%, X7R, AEC-Q200 Grade 1, 0603", Cap_Case=0603, Manufacturer=MuRata, Supplier Part Number 1=490-8015-1-ND, TempCo=X7R, Tolerance_%=10%, Value1=Unknown, Value2=16V, ValueDisplayed=0.1uF
C19 C21 C25 C29 C31: library part CMP-0007965-1, "CAP, CERM, 10 uF, 16 V, +/- 10%, X7S, AEC-Q200 Grade 1, 0805", Cap_Case=0805, Manufacturer=TDK, Supplier Part Number 1=445-16110-1-ND, TempCo=X7S, Tolerance_%=10%, Value1=Unknown, Value2=16V, ValueDisplayed=10uF
C20 C26 C32: library part CMP-0085979-1, "CAP, CERM, 22 µF, 6.3 V,+/- 20%, X7R, AEC-Q200 Grade 1, 1206", Cap_Case=1206, Manufacturer=MuRata, TempCo=X7R, Tolerance_%=20%, Value2=6.3V, ValueDisplayed=22µF
C23: library part CMP-0007072-2, "CAP, CERM, 220 pF, 20 V, +/- 5%, C0G/NP0, AEC-Q200 Grade 1, 0603", Cap_Case=0603, Manufacturer=TDK, Supplier Part Number 1=445-5644-1-ND, TempCo=C0G/NP0, Tolerance_%=5%, Value1=Unknown, Value2=20V, ValueDisplayed=220pF
C28 C34 C35 C37: library part CMP-0006350-2, "CAP, CERM, 0.1 uF, 10 V, +/- 10%, X7R, AEC-Q200 Grade 1, 0402", Cap_Case=0402, Manufacturer=MuRata, Supplier Part Number 1=81-GCM155R71A104K5D, TempCo=X7R, Tolerance_%=10%, Value1=Unknown, Value2=10V, ValueDisplayed=0.1uF
C30 C36 C42: library part CMP-0860290-1, "CAP, CERM, 10 pF, 50 V,+/- 5%, C0G/NP0, AEC-Q200 Grade 1, 0402", Cap_Case=0402, Manufacturer=MuRata, TempCo=C0G/NP0, Tolerance_%=5%, Value2=50V, ValueDisplayed=10pF
GND TP8 TP11 TP14 TP16 TP17 TP18 TP19: library part CMP-0055148-1, "Test Point, Multipurpose, Black, TH", Color=Black, Manufacturer=Keystone, Supplier Part Number 1=36-5011-ND
J1 J3 J6 J7 J8 J10 J12 J14: library part CMP-0055086-1, "Header, 100mil, 3x1, TH", Manufacturer=Mill-Max, Supplier Part Number 1=ED7203-ND
J2: library part CMP-0055167-2, "Standard Banana Jack, Insulated, Red", Manufacturer=Keystone, Supplier Part Number 1=36-6091-ND
J4 J17: library part CMP-0002337-1, "Header, 100mil, 2x1, Tin, TH", Color=Black, Current_A=3A, Manufacturer="Sullins Connector Solutions", Supplier Part Number 1=S1012E-02-ND, Voltage_V=1.8kV
J5: library part CMP-0055168-2, "Standard Banana Jack, Insulated, Black", Manufacturer=Keystone, Supplier Part Number 1=36-6092-ND
J9 J11 J13 J15: library part CMP-0054825-1, "Terminal Block, 3.5mm, 2x1, Tin, TH", Color=Green, Current_A=10A, Manufacturer="Wurth Elektronik", Supplier Part Number 1=732-2747-ND, Voltage_V=300V
J16: library part CMP-0055087-1, "Header, 100mil, 4x1, TH", Manufacturer=Mill-Max, Supplier Part Number 1=ED7204-ND
L1: library part CMP-0058725-1, "Inductor, Wirewound, Ferrite, 1.5 uH, 4.5 A, 0.0168 ohm, SMD", Manufacturer=MuRata, Value1="0.0168 ohm", Value2=4.5A, ValueDisplayed=1.5uH
L2 L4: library part CMP-0003374-1, "Ferrite Bead, 600 ohm @ 100 MHz, 3 A, 1210", Manufacturer="Taiyo Yuden", Supplier Part Number 1=587-1755-1-ND, Value1="0.042 ohm", Value2=3A, ValueDisplayed="600 ohm"
L3: library part CMP-0058726-1, "Inductor, Wirewound, Ferrite, 2.2 uH, 4.3 A, 0.0192 ohm, SMD", Manufacturer=MuRata, Value1="0.0192 ohm", Value2=4.3A, ValueDisplayed=2.2uH
L5 L6 L7 L8: library part CMP-0080779-1, "Inductor, Shielded, Metal Composite, 470 nH, 4.5 A, 0.026 ohm, SMD", Manufacturer=MuRata, PartNumber=DFE201612E-R47M{}P2, Value1="0.026 ohm", Value2=4.5A, ValueDisplayed=470nH
Logo1: library part CMP-0074769-1
Logo2: library part CMP-0074847-1, "FCC_disclaimer"
R1: library part CMP-0020720-3, "RES, 3.0, 5%, 0.125 W, AEC-Q200 Grade 0, 0805", Manufacturer=Panasonic, Power_W=125mW, Supplier Part Number 1=P3.0ACT-ND, TempCo="600 ppm/C", Tolerance_%=5%, Value2=0.125W, Value_Code=3R00, ValueDisplayed=3.0
R2 R6 R7 R8 R17 R21 R27 R33: library part CMP-0026753-1, "RES, 100 k, 1%, 0.063 W, AEC-Q200 Grade 0, 0402", Manufacturer="Stackpole Electronics Inc", Power_W=63mW, Supplier Part Number 1=RMCF0402FT100KCT-ND, TempCo="100 ppm/C", Tolerance_%=1%, Value2=0.063W, Value_Code=100k
R3 R11 R14 R18 R24: library part CMP-0081856-1, "RES, 0, 0%, 0.2 W, AEC-Q200 Grade 0, 0402", Manufacturer=Vishay-Dale, Power_W=200mW, Supplier Part Number 1=541-0.0YBTR-ND, Tolerance_%=0%, Value2=0.2W, Value_Code=0
R4: library part CMP-0022717-2, "RES, 0.51, 1%, 0.1 W, AEC-Q200 Grade 1, 0603", Manufacturer=Panasonic, Power_W=100mW, Supplier Part Number 1=P.51AJCT-ND, TempCo="300 ppm/C", Tolerance_%=1%, Value2=0.1W, Value_Code=R510, ValueDisplayed=0.51
R5 R16 R19 R25 R31: library part CMP-0026703-1, "RES, 49.9, 1%, 0.1 W, AEC-Q200 Grade 0, 0402", Manufacturer=Panasonic, Power_W=100mW, Supplier Part Number 1=P49.9LCT-ND, TempCo="100 ppm/C", Tolerance_%=1%, Value2=0.1W, Value_Code=49R9, ValueDisplayed=49.9
R9 R13 R15 R20 R26 R32: library part CMP-0025958-3, "RES, 10.0 k, 1%, 0.063 W, AEC-Q200 Grade 0, 0402", Manufacturer=Vishay-Dale, Power_W=63mW, Supplier Part Number 1=541-10.0KLCT-ND, TempCo="100 ppm/C", Tolerance_%=1%, Value2=0.063W, Value_Code=10k0, ValueDisplayed=10.0k
R10 R12: library part CMP-0086176-1, "RES, 0, 0.75 W, AEC-Q200 Grade 0, 1206", Manufacturer=Vishay-Dale, Power_W=750mW, Tolerance_%=0%, Value2=0.75W, Value_Code=0
R22: library part CMP-0026182-2, "RES, 232 k, 1%, 0.063 W, AEC-Q200 Grade 0, 0402", Manufacturer=Vishay-Dale, Power_W=63mW, Supplier Part Number 1=541-232KLCT-ND, TempCo="100 ppm/C", Tolerance_%=1%, Value2=0.063W, Value_Code=232k
R23 R29 R35: library part CMP-0026705-1, "RES, 51.0 k, 1%, 0.1 W, AEC-Q200 Grade 0, 0402", Manufacturer=Panasonic, Power_W=100mW, Supplier Part Number 1=P51.0KLCT-ND, TempCo="100 ppm/C", Tolerance_%=1%, Value2=0.1W, Value_Code=51k0, ValueDisplayed=51.0k
R28: library part CMP-0026498-2, "RES, 64.9 k, 1%, 0.063 W, AEC-Q200 Grade 0, 0402", Manufacturer=Vishay-Dale, Power_W=63mW, Supplier Part Number 1=541-64.9KLCT-ND, TempCo="100 ppm/C", Tolerance_%=1%, Value2=0.063W, Value_Code=64k9, ValueDisplayed=64.9k
R30: library part CMP-0081857-1, "RES, 0, 0%,  W, AEC-Q200 Grade 0, 0805", Manufacturer=Rohm, Supplier Part Number 1=755-PMR10EZPJ000, Tolerance_%=0%, Value2=W, Value_Code=0
R34: library part CMP-0026702-1, "RES, 49.9 k, 1%, 0.1 W, AEC-Q200 Grade 0, 0402", Manufacturer=Panasonic, Power_W=100mW, Supplier Part Number 1=P49.9KLCT-ND, TempCo="100 ppm/C", Tolerance_%=1%, Value2=0.1W, Value_Code=49k9, ValueDisplayed=49.9k
R36: library part CMP-0022333-5, "RES, 324, 1%, 0.1 W, AEC-Q200 Grade 0, 0603", Manufacturer=Vishay-Dale, Power_W=100mW, Supplier Part Number 1=541-324HCT-ND, TempCo="100 ppm/C", Tolerance_%=1%, Value2=0.1W, Value_Code=324R, ValueDisplayed=324
TP1 TP5 TP7 TP10 TP13: library part CMP-0055151-1, "Test Point, Multipurpose, Yellow, TH", Color=Yellow, Manufacturer=Keystone, Supplier Part Number 1=36-5014-ND
TP2 TP3 TP4 TP6 TP9 TP12 TP15 VBAT: library part CMP-0055147-1, "Test Point, Multipurpose, Red, TH", Color=Red, Manufacturer=Keystone, Supplier Part Number 1=36-5010-ND
U1: library part CMP-0861031-1, "3.5-V to 36-V, 2.5-A, Automotive Step-down Voltage Converter, DRR0012E (WSON-12)", Alternate Manufacturer="Texas Instruments"
U2: library part CMP-0860155-1, "Automotive capacitor-free 300-mA LDO regulator with foldback current limit for portable devices, DBV0005A (SOT-23-5)", Alternate Manufacturer="Texas Instruments", Operating Temperature Range="-40 to 125,-40 to 150 C", Rating=Automotive
U3: library part CMP-0073677-2, "5.5V, 4A, 16mO Automotive Load Switch With Adjustable Rise Time and Optional Quick Output Discharge, DSG0008B (WSON-8)", Alternate Manufacturer="Texas Instruments"
U4: library part CMP-0088309-1, "2.7-V to 6-V Adjustable-Frequency Step-Down Converter in SOT583 Package", Manufacturer="Texas Instruments", Max Supply Voltage=6V, Min Supply Voltage=2.7V, Nominal Supply Current=15uA, Operating Temperature Range="-40°C to +150°C", Output Voltage=1.8V, Switching Frequency=1.8-3.5MHz
U5 U6: library part CMP-0088310-1, "2.7-V to 6-V Adjustable-Frequency Step-Down Converter in SOT583 Package", Manufacturer="Texas Instruments", Max Supply Voltage=6V, Min Supply Voltage=2.7V, Nominal Supply Current=15uA, Operating Temperature Range="-40°C to +150°C", Output Voltage=0.6-5.5V, Switching Frequency=1.8-3.5MHz
U7: library part CMP-0088303-1, "2.7-V to 6-V Adjustable-Frequency Step-Down Converter in SOT583 Package", Manufacturer="Texas Instruments", Max Supply Voltage=6V, Min Supply Voltage=2.7V, Nominal Supply Current=15uA, Operating Temperature Range="-40°C to +150°C", Output Voltage=0.5-5.5V, Switching Frequency=1.8-3.5MHz

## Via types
v1: diameter 20, hole 10, Top Layer to Bottom Layer, 207 vias
v2: diameter 19.68, hole 7.87, Top Layer to Bottom Layer, 5 vias

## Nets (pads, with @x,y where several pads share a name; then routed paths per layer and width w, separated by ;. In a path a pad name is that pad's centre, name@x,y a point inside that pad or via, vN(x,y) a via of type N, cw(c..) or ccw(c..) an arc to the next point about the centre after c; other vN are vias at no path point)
1V8: C20.1 C28.1 J9.1 L5.2 R16.2 R17.2 TP4.1 | length 1562.2
  Top Layer w10: R16.2@1749.75,1909.02 R16.2@1750.74,1908.04
  Top Layer w20: R17.2@478.15,970.47 v1(478.15,1019.68)
  Signal Layer 3 w10: v1(478.15,1019.68) 500,1019.68 1047.24,1566.93 1047.24,1669.5 1386.94,2009.2 1499.36,2009.2 v1(1513.78,2023.62)
  other v1: 1590.55,1928.48
1V35: C26.1 C35.1 J13.1 L7.2 R25.2 R27.2 TP9.1 | length 2394.4
  Top Layer w10: v1(1219.49,935.63) v1@1220.26,934.86 ; C35.1@1297.64,864.76 C35.1@1297.86,864.98
  Top Layer w20: R27.2@275.59,972.44 275.59,1019.1 v1(276.17,1019.68)
  Signal Layer 3 w10: v1(276.17,1019.68) 276.17,1047.24 221.77,1101.65 109.52,1101.65 82.68,1074.8 82.68,98.43 98.43,82.68 996.06,82.68 1068.63,155.24 J13.1@1068.63,247.19
  other v1: 1272.27,866.13
1V175: C32.1 C37.1 J15.1 L8.2 R31.2 R33.2 TP12.1 | length 3045.1
  Top Layer w20: R33.2@176.69,970.47 176.69,1019.2 v1(177.17,1019.68)
  Signal Layer 3 w10: v1(177.17,1019.68) 177.17,1051.18 161.42,1066.93 122.05,1066.93 114.17,1059.06 114.17,153.54 122.05,145.67 535.43,145.67 830.71,440.94 1420.31,440.94 1433.07,453.71 1433.07,712.6 1539.25,818.78 1555.12,834.65 1560.91,840.44 v1(1657.39,840.44)
  other v1: 1658.6,807.09 1612.96,864.76 1612.96,898.79
3.3V_LDO: C15.1 J17.1 R36.2 TP3.1 U2.5 | length 939.4
  Top Layer w20: C15.1@2010.36,1359.54 2074.78,1359.54 2161.42,1272.9 2161.42,577.35 TP3.1@2201.68,537.09
3V3_Buck: C24.1 C34.1 J11.1 L6.2 R19.2 R21.2 TP6.1 | length 2148.1
  Top Layer w20: R21.2@377.95,972.44 v1(377.95,1017.77)
  Signal Layer 3 w10: v1(377.95,1017.77) 434.99,1074.8 509.18,1074.8 1000,1565.62 1000,1661.52 1401.47,2062.99 1930.33,2062.99 v1(1973.64,2019.68)
  other v1: 2051.18,1841.81 2051.18,1925.2 2006.26,1980.32
5V_LS: C18.1 R14.1 R15.1 R18.1 R20.1 R24.1 R26.1 R30.1 R32.1 TP15.1 U3.7 U3.8 | length 2844.5
  Top Layer w20: R14.1@1638.69,1677.9 1662.93,1653.66 v1(1677.91,1653.66) 1708.54,1653.66 v1(1708.66,1653.54) ; R18.1@1959.31,1556.03 1970.47,1544.86 U3.8@1970.47,1503.86 U3.7@1970.47,1487.28 ; TP15.1@2358.27,1850.39 2580.52,2072.65 2743.01,2072.65 R15.1@2743.01,2331.81 ; v1(2653.54,595.59) R32.1@2701.8,595.59 2701.8,322.01 R26.1@2703.58,320.23
  Top Layer w40: R24.1@1439.47,1212.65 1469.55,1212.65 ; 1788.32,1208.35 R30.1@1830.85,1208.35
  Signal Layer 3 w10: v1(1793.67,1218.47) 1795.68,1220.47 1972.44,1220.47 2597.33,595.59 v1(2653.54,595.59)
  Signal Layer 3 w20: v1@1705.11,1652.59 1707.63,1650.08 1708.66,1651.11 v1(1708.66,1653.54) ; v1(2067.5,1551.42) 2067.56,1551.49 2087.71,1551.49 2358.27,1822.04 TP15.1@2358.27,1850.39
  other v1: 1792.07,1196.47 1476.38,1196.74 1476.38,1225.7 2039.37,1551.49
CBOOT: R3.2 U1.2 | length 41
  Top Layer w10: U1.2@1286.32,1621.35 1286.32,1655.56 1289.98,1659.22 R3.2@1289.98,1660.86
CGND: C5.2 GND.1 J5.1 L4.1 | length 87
  Top Layer w35: C5.2@783.48,1918.43 817.84,1918.43 824.11,1912.16 L4.1@824.11,1868.41
EN_1V8: J8.2 U4.2 | length 1533.5
  Top Layer w10: U4.2@1664.3,1737.97 1664.3,1713.92 1683.99,1694.24 v1(1683.99,1685.04)
  Bottom Layer w10: v1(1683.99,1685.04) 1683.99,1697.8 1983,1996.81 1983.11,1996.81 1996.51,2010.21 1996.51,2010.33 2021.62,2035.43 2751.91,2035.43 2893.65,2177.17 J8.2@2893.65,2228.51
EN_1V35: J12.2 U6.2 | length 2050.9
  Top Layer w10: U6.2@1299.83,1172.88 v1@1299.83,1203.27
  Top Layer w20: v1(1299.47,1203.63) v1@1299.83,1203.27
  Bottom Layer w10: v1(1299.47,1203.63) 1402.07,1101.03 2062.3,1101.03 2852.59,310.74 J12.2@2852.59,213.69
EN_1V175: J14.2 U7.2 | length 1583.2
  Top Layer w10: v1(1684.95,1189.6) 1688.97,1185.58 U7.2@1688.97,1143.75
  Bottom Layer w10: v1(1684.95,1189.6) 1684.95,1150.76 1703.4,1132.31 2147.22,1132.31 2649.61,629.92 2801.41,629.92 2853.64,577.69 J14.2@2853.64,486.95
EN_3V3_Buck: J10.2 U5.2 | length 1144.7
  Top Layer w10: U5.2@1988.4,1627.17 1988.4,1593.99 v1(2001.04,1581.35)
  Bottom Layer w10: v1(2001.04,1581.35) 2203.15,1783.46 2795.22,1783.46 2895.32,1883.57 J10.2@2895.32,1957.78
EN_3V3_LDO: J6.2 U2.3 | length 1271
  Top Layer w10: v1(1846.46,1257.77) 1847.16,1258.47 U2.3@1847.16,1288.58
  Bottom Layer w10: v1(1846.46,1257.77) 1848.53,1259.84 2052.95,1259.84 2107.08,1205.72 2164.66,1205.72 2535.73,834.65 2829.25,834.65 2848.93,814.96 J6.2@2848.93,762.65
EN_5V_Buck: J1.2 U1.10 | length 1424.6
  Top Layer w10: U1.10@1266.63,1511.9 1266.63,1485.92 v1(1276.48,1476.07)
  Bottom Layer w10: J1.2@327.16,613.55 441.96,728.35 615.8,728.35 1165.3,1277.85 1211.65,1277.85 1276.48,1342.67 v1(1276.48,1476.07)
FB_5V: R5.1 TP1.1 U1.8 | length 1973.1
  Top Layer w10: v1(1213.49,1476.07) 1227.26,1489.84 U1.8@1227.26,1511.9 ; v1(1636.72,1480) v1@1638.69,1478.04
  Top Layer w15: R5.1@1638.69,1445.76 v1@1638.69,1478.04
  Signal Layer 3 w10: v1(1636.72,1480) 1833.55,1480 1844.04,1469.52 1844.04,1455.01 1857.44,1441.62 1871.94,1441.62 2093.68,1219.88 2093.68,1219.12 2107.08,1205.72 2107.84,1205.72 2245.53,1068.03 TP1.1@2860.66,1068.03
  Bottom Layer w10: v1(1213.49,1476.07) 1237.42,1500 1293.02,1500 1375.3,1417.72 1574.43,1417.72 v1(1636.72,1480)
GND: C3.2 C6.2 C7.2 C8.2 C9.2 C10.2 C11.2 C12.2 C13.2 C14.2 C15.2 C16.2 C17.2 C18.2 C19.2 C20.2 C21.2 C22.2 C23.2 C24.2 C25.2 C26.2 C27.2 C28.2 C29.2 C31.2 C32.2 C33.2 C34.2 C35.2 C37.2 C38.2 J1.3 J4.2 J6.3 J7.3 J8.3 J9.2 J10.3 J11.2 J12.3 J13.2 J14.3 J15.2 J17.2 L4.2 R1.1 R4.1 R7.1 R23.1 R29.1 R35.1 R36.1 TP8.1 TP11.1 TP14.1 TP16.1 TP17.1 TP18.1 TP19.1 U1.4 U1.9 U1.11 U1.13 U2.2 U2.4 U3.5 U3.9 U4.4 U4.8 U5.4 U5.8 U6.4 U6.8 U7.4 U7.8 | length 9797.3
  Top Layer w8: R7.1@227.16,379.47 R7.1@228.35,378.29 ; U6.4@1260.46,1172.88 1260.46,1158.02 1261.36,1157.11 1261.36,1146.95 1264.57,1143.75 1314.77,1143.75 1320.14,1138.38 U6.8@1320.14,1114.62 ; U7.4@1649.6,1143.75 1649.6,1120.8 1656.42,1113.98 1697.37,1113.98 1708.66,1102.7 U7.8@1708.66,1085.48 ; J12.3@2952.59,213.69 J12.3@2953.64,214.74
  Top Layer w10: U1.4@1246.95,1621.35 1246.95,1576.47 U1.13@1256.79,1566.63 ; C10.2@1268.61,1444.57 1246.95,1466.23 U1.9@1246.95,1511.9 1246.95,1556.78 U1.13@1256.79,1566.63 ; U1.11@1286.24,1511.9 1286.24,1537.18 U1.13@1256.79,1566.63
  Top Layer w35: L4.2@824.11,1738.49 897.83,1738.49 927.19,1709.14 R4.1@927.19,1679.44 927.19,1620.1 889.72,1582.64 C3.2@835.3,1582.64 821.96,1569.3 C6.2@821.96,1521.96 840.14,1521.96 858.27,1503.83 v1(858.27,1474.33)
  Top Layer w40: R7.1@227.16,379.47 J1.3@227.16,613.55 ; R7.1@228.35,378.29 123.33,378.29 82.68,337.64 82.68,160.43 121.06,122.05 665.35,122.05 791.34,248.03 791.34,751.97 v1(905.51,866.14) ; J13.2@1206.42,247.19 1206.42,469.63 TP11.1@1137.53,538.53 1345.1,746.11 C35.2@1345.1,864.98 ; v1(1417.63,2086.61) 1420.14,2089.12 TP18.1@1420.14,2228.35 1420.14,2448.82 1471.32,2500 J9.2@1565.51,2500 ; v1(1769.42,806.79) 1791.34,784.86 TP14.1@1791.34,537.4 1868.58,460.16 J15.2@1868.58,259.84 ; v1(2086.61,2086.61) 2106.85,2106.85 TP8.1@2106.85,2216.54 2106.85,2406.06 2196.85,2496.06 J11.2@2253.16,2496.06 ; R23.1@2095.52,1630.66 2129.16,1630.66 2154.86,1656.36 TP16.1@2360.54,1656.36 2441.05,1656.36 2468.5,1628.91 2468.5,1370.01 2437.71,1339.21 J4.2@2366.69,1339.21 ; v1(2224.33,748.03) 2322.83,748.03 2421.26,649.61 TP17.1@2421.26,537.4 2338.58,454.72 R36.1@2338.58,345.47 2354.33,329.72 J17.2@2354.33,235.24 2354.33,141.26 2440.48,55.12 2909.45,55.12 2952.59,98.26 J12.3@2952.59,213.69 ; TP19.1@2860.66,1264.88 2980.91,1264.88 v1@2985.94,1259.84 ; J12.3@2953.64,214.74 J14.3@2953.64,486.95 2953.64,757.95 J6.3@2948.93,762.65 2985.94,799.66 v1@2985.94,1259.84 ; J8.3@2993.65,2228.51 2995.32,2226.83 J10.3@2995.32,1957.78 2995.32,1677.73 J7.3@2985.94,1668.34 v1@2985.94,1259.84
  other v1: 1334.65,746.71 1062.99,748.03 1141.73,748.03 1255.91,748.03 1413.39,748.03 1728.35,748.03 1807.09,748.03 1889.76,748.03 1969.43,748.03 2047.24,748.03 2126.91,748.03 1736.34,781.81 2224.33,803.04 1781.16,837.38 1813.37,849.94 1385.83,864.46 2224.33,881.78 1813.37,883.44 1423.72,909.45 1813.37,913.39 1776.57,940.94 1423.72,944.27 1766.46,1004.62 1798.25,1004.62 1859.19,1004.62 1891.73,1004.62 1941.56,1014.74 1970.47,1014.58 2224.41,1015.75 1391.26,1017.77 1422.26,1018.7 1452.76,1029.81 1728.35,1063.04 1342.52,1090.21 905.51,1114.17 1623.95,1155.54 1230.21,1193.07 2224.33,1196.74 1515.87,1227.97 1543.9,1228.15 1575.54,1228.59 1608.24,1228.59 1782.48,1253.02 2984.84,1264.88 2224.33,1275.48 2051.18,1295.79 1153.54,1304.25 2051.18,1324.8 2224.33,1354.22 1209.54,1434.05 1227.91,1447.76 590.55,1456.38 1184.04,1458.65 2129.2,1486.29 511.81,1494.89 1390.38,1548.5 1421.53,1547.66 1455.01,1547.66 1489.43,1548.5 1520.57,1548.5 1549.86,1548.5 2129.92,1550.87 1340.57,1552.79 1237.19,1555.23 1277.37,1556.03 1186.68,1557.16 1771.65,1559.06 1856.05,1560.15 1161.42,1569.65 511.81,1573.63 1327.65,1578.41 1237.19,1578.74 1276.48,1578.74 1186.68,1586.61 1023.62,1615.47 511.81,1653.54 1944.9,1710.38 1248.03,1728.35 1023.62,1730.82 511.81,1732.28 1884.95,1734.94 1804.23,1746.37 1832.46,1746.38 1456.69,1774.56 1023.62,1808.78 511.81,1811.02 1455.75,1810.55 1621,1813.37 1461.48,1847.37 1460.63,1870.08 1023.62,1888.3 196.85,1890.32 275.59,1890.32 354.33,1890.32 433.07,1889.76 511.81,1890.87 1062.99,1928.48 1141.73,1928.48 1220.47,1928.48 1856.28,1929.69 1887.3,1963.15 157.48,1968.5 1260.46,1968.5 1886.96,1991.68 1259.56,2046.4 157.48,2047.24 1336.94,2086.61 1496.06,2086.61 1850.72,2086.61 1929.13,2087.07 2008.09,2087.07 1260.46,2125.14 157.48,2125.98 1968.5,2125.98 1259.32,2203.88 157.48,2204.72 157.48,2283.46 1260.46,2283.46 1259.86,2360.2 157.48,2362.2 157.48,2440.94 1260.46,2440.94 157.48,2519.68 1260.46,2519.68 157.48,2598.43 1260.46,2598.43 157.48,2677.17 1260.46,2677.17
  other v2: 1933.07,1452.68 1933.07,1495.99 1256.79,1565.63 1217.42,1566.63 1296.16,1566.63
NetC1_1: C1.1 R1.2 | length 62.5
  Top Layer w10: R1.2@1646.48,1621.35 R1.2@1662.62,1605.21
  Top Layer w15: C1.1@1606.85,1621.35 R1.2@1646.48,1621.35
NetC2_1: C2.1 C3.1 C6.1 L1.1 L2.2 | length 404.6
  Top Layer w35: L2.2@691.03,1738.49 671.3,1718.76 671.3,1668.2 C2.1@673.25,1666.25 673.25,1609.88 700.49,1582.64 C3.1@755.3,1582.64 755.3,1541.38 C6.1@774.72,1521.96 774.72,1451.44 L1.1@750.34,1427.06
NetC2_2: C2.2 R4.2 | length 62.5
  Top Layer w10: C2.2@807.11,1666.25 C2.2@820.29,1679.44
  Top Layer w35: C2.2@820.29,1679.44 R4.2@864.19,1679.44
NetC4_1: C4.1 R3.1 | length 98.8
  Top Layer w15: R3.1@1289.98,1700.86 1289.98,1742.35 1299.29,1751.66 C4.1@1343.41,1751.66
NetC13_1: C13.1 R11.2 U2.1 | length 127.6
  Top Layer w20: R11.2@1728.26,1279.53 1747.38,1279.53 1759.27,1291.42 1759.27,1319.09 1794.52,1354.33 C13.1@1795.85,1354.33 C13.1@1804.9,1363.39
NetC16_1: C16.1 R12.2 U3.1 U3.2 U3.4
  other v1: 1818.89,1452.75 1796.9,1455.13 1691.79,1555.38 1732.28,1554.51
